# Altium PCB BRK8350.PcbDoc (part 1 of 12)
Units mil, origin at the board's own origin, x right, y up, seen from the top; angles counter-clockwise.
Board outline 9448.82 x 5905.51 mil, 8 copper layers (L1-TOP, L2-GND, L3-SIG, L4-GND, L5-PWR, L6-PWR, L7-GND, L8-BOT), stack 57.69 mil thick; 288 components, 543 nets, 1891 pads, 2032 vias.
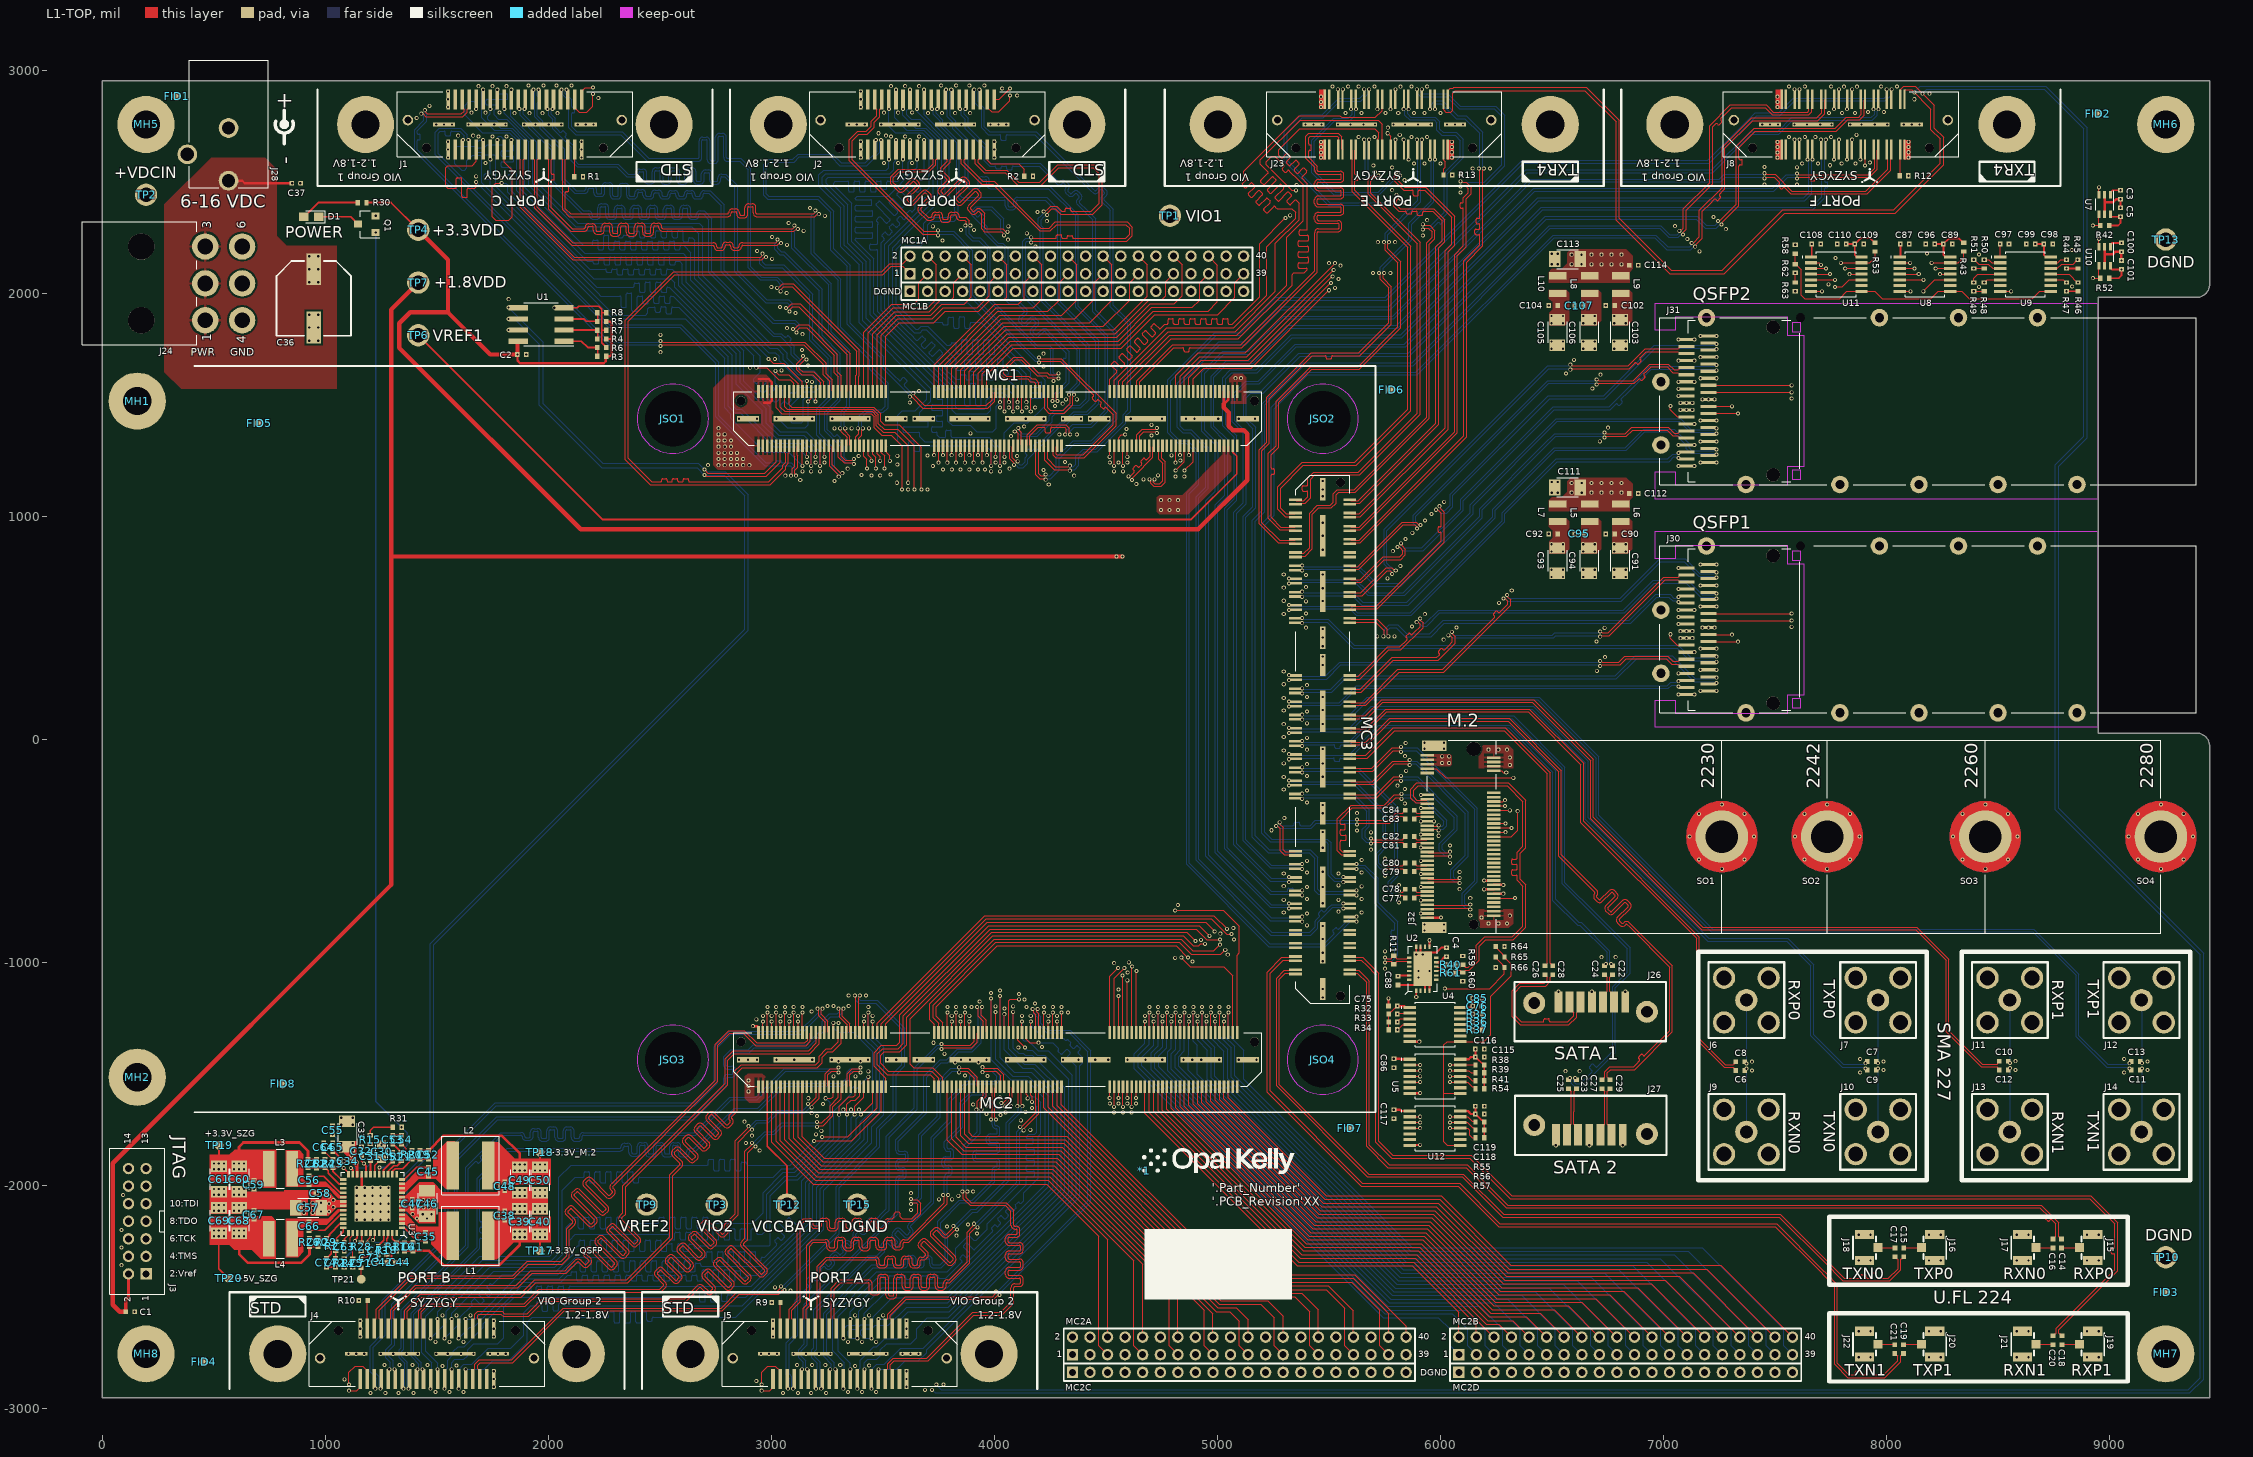
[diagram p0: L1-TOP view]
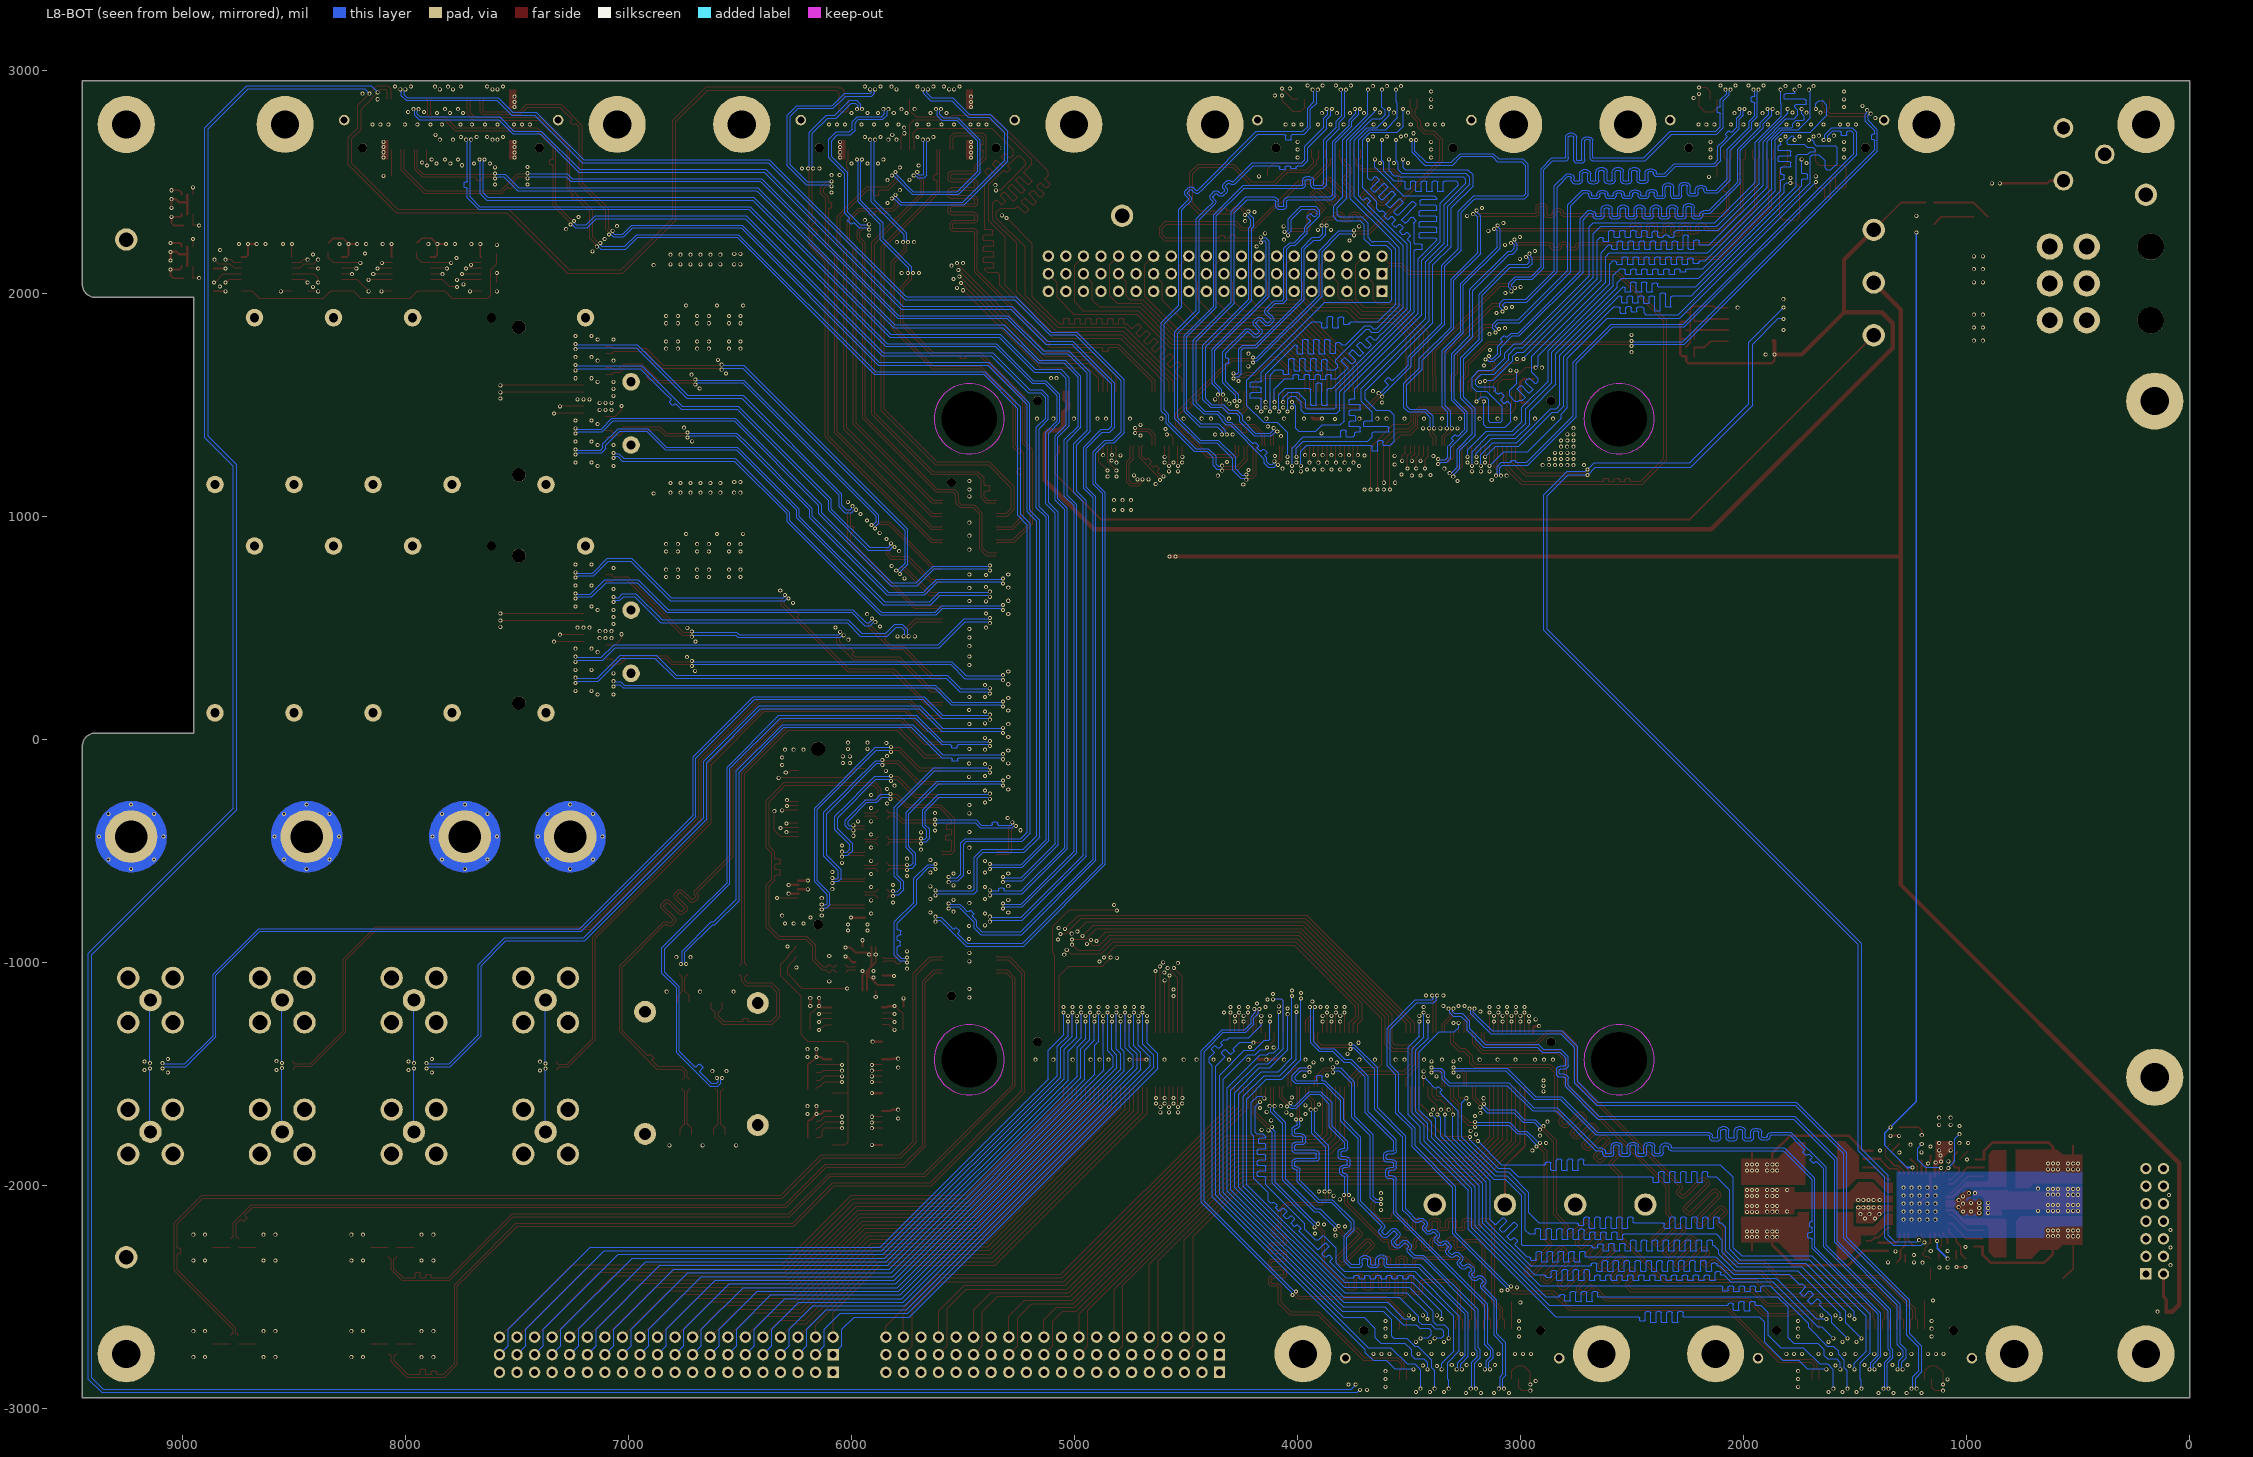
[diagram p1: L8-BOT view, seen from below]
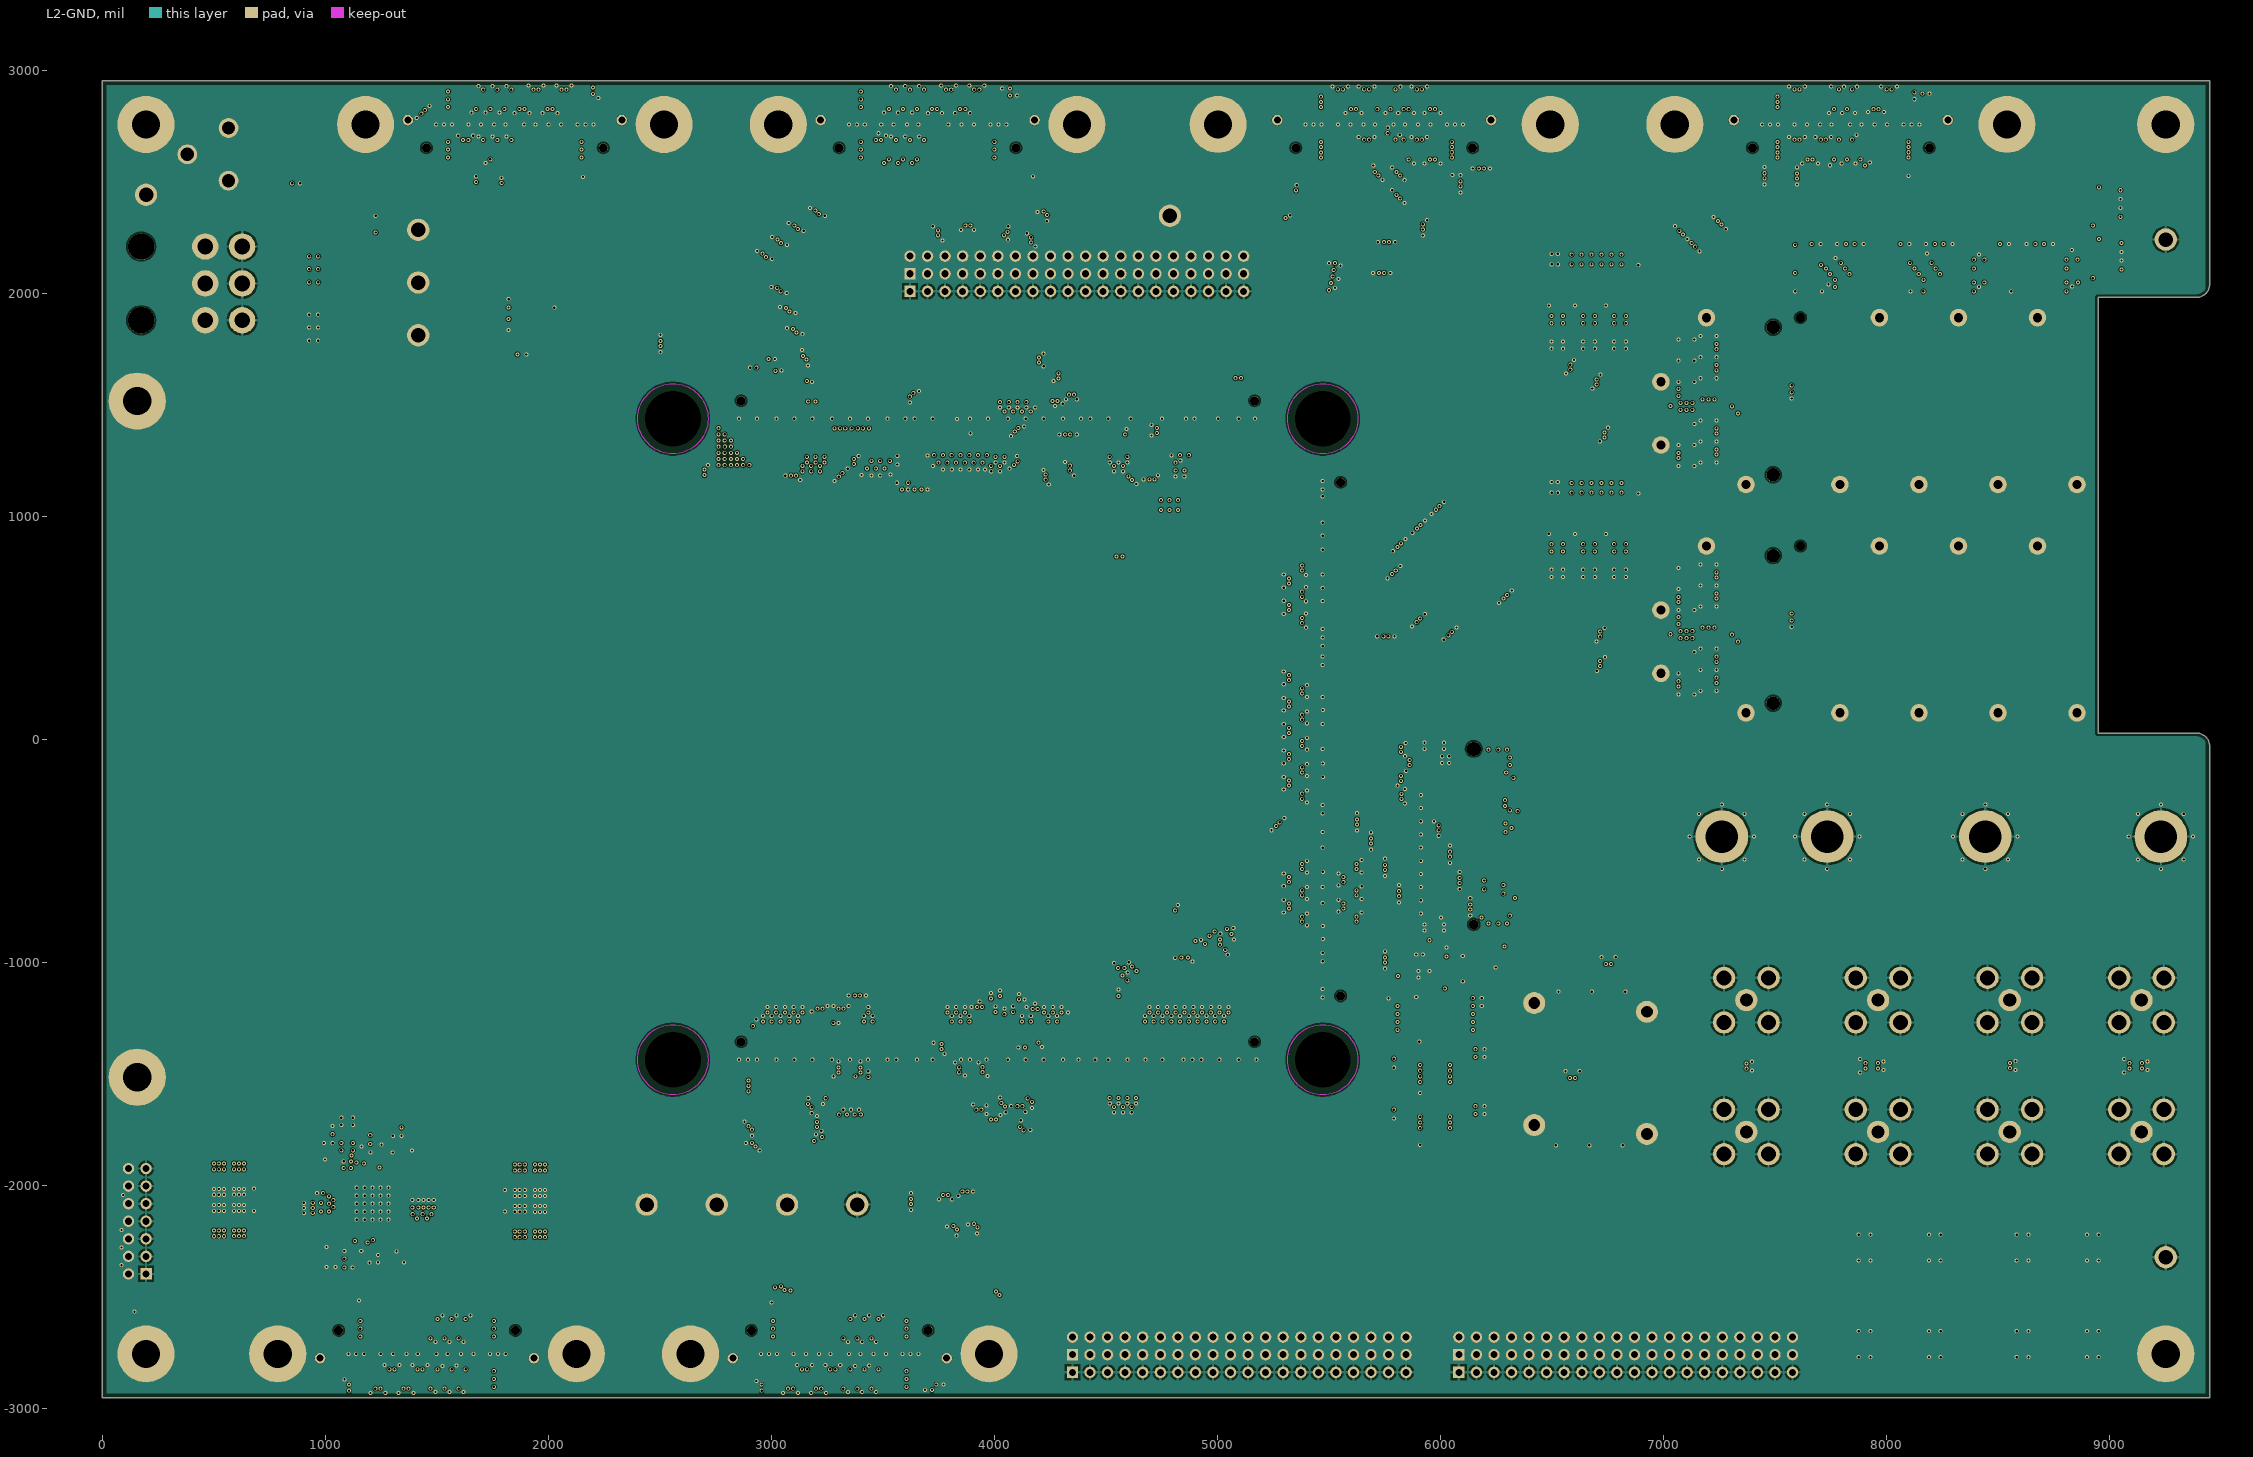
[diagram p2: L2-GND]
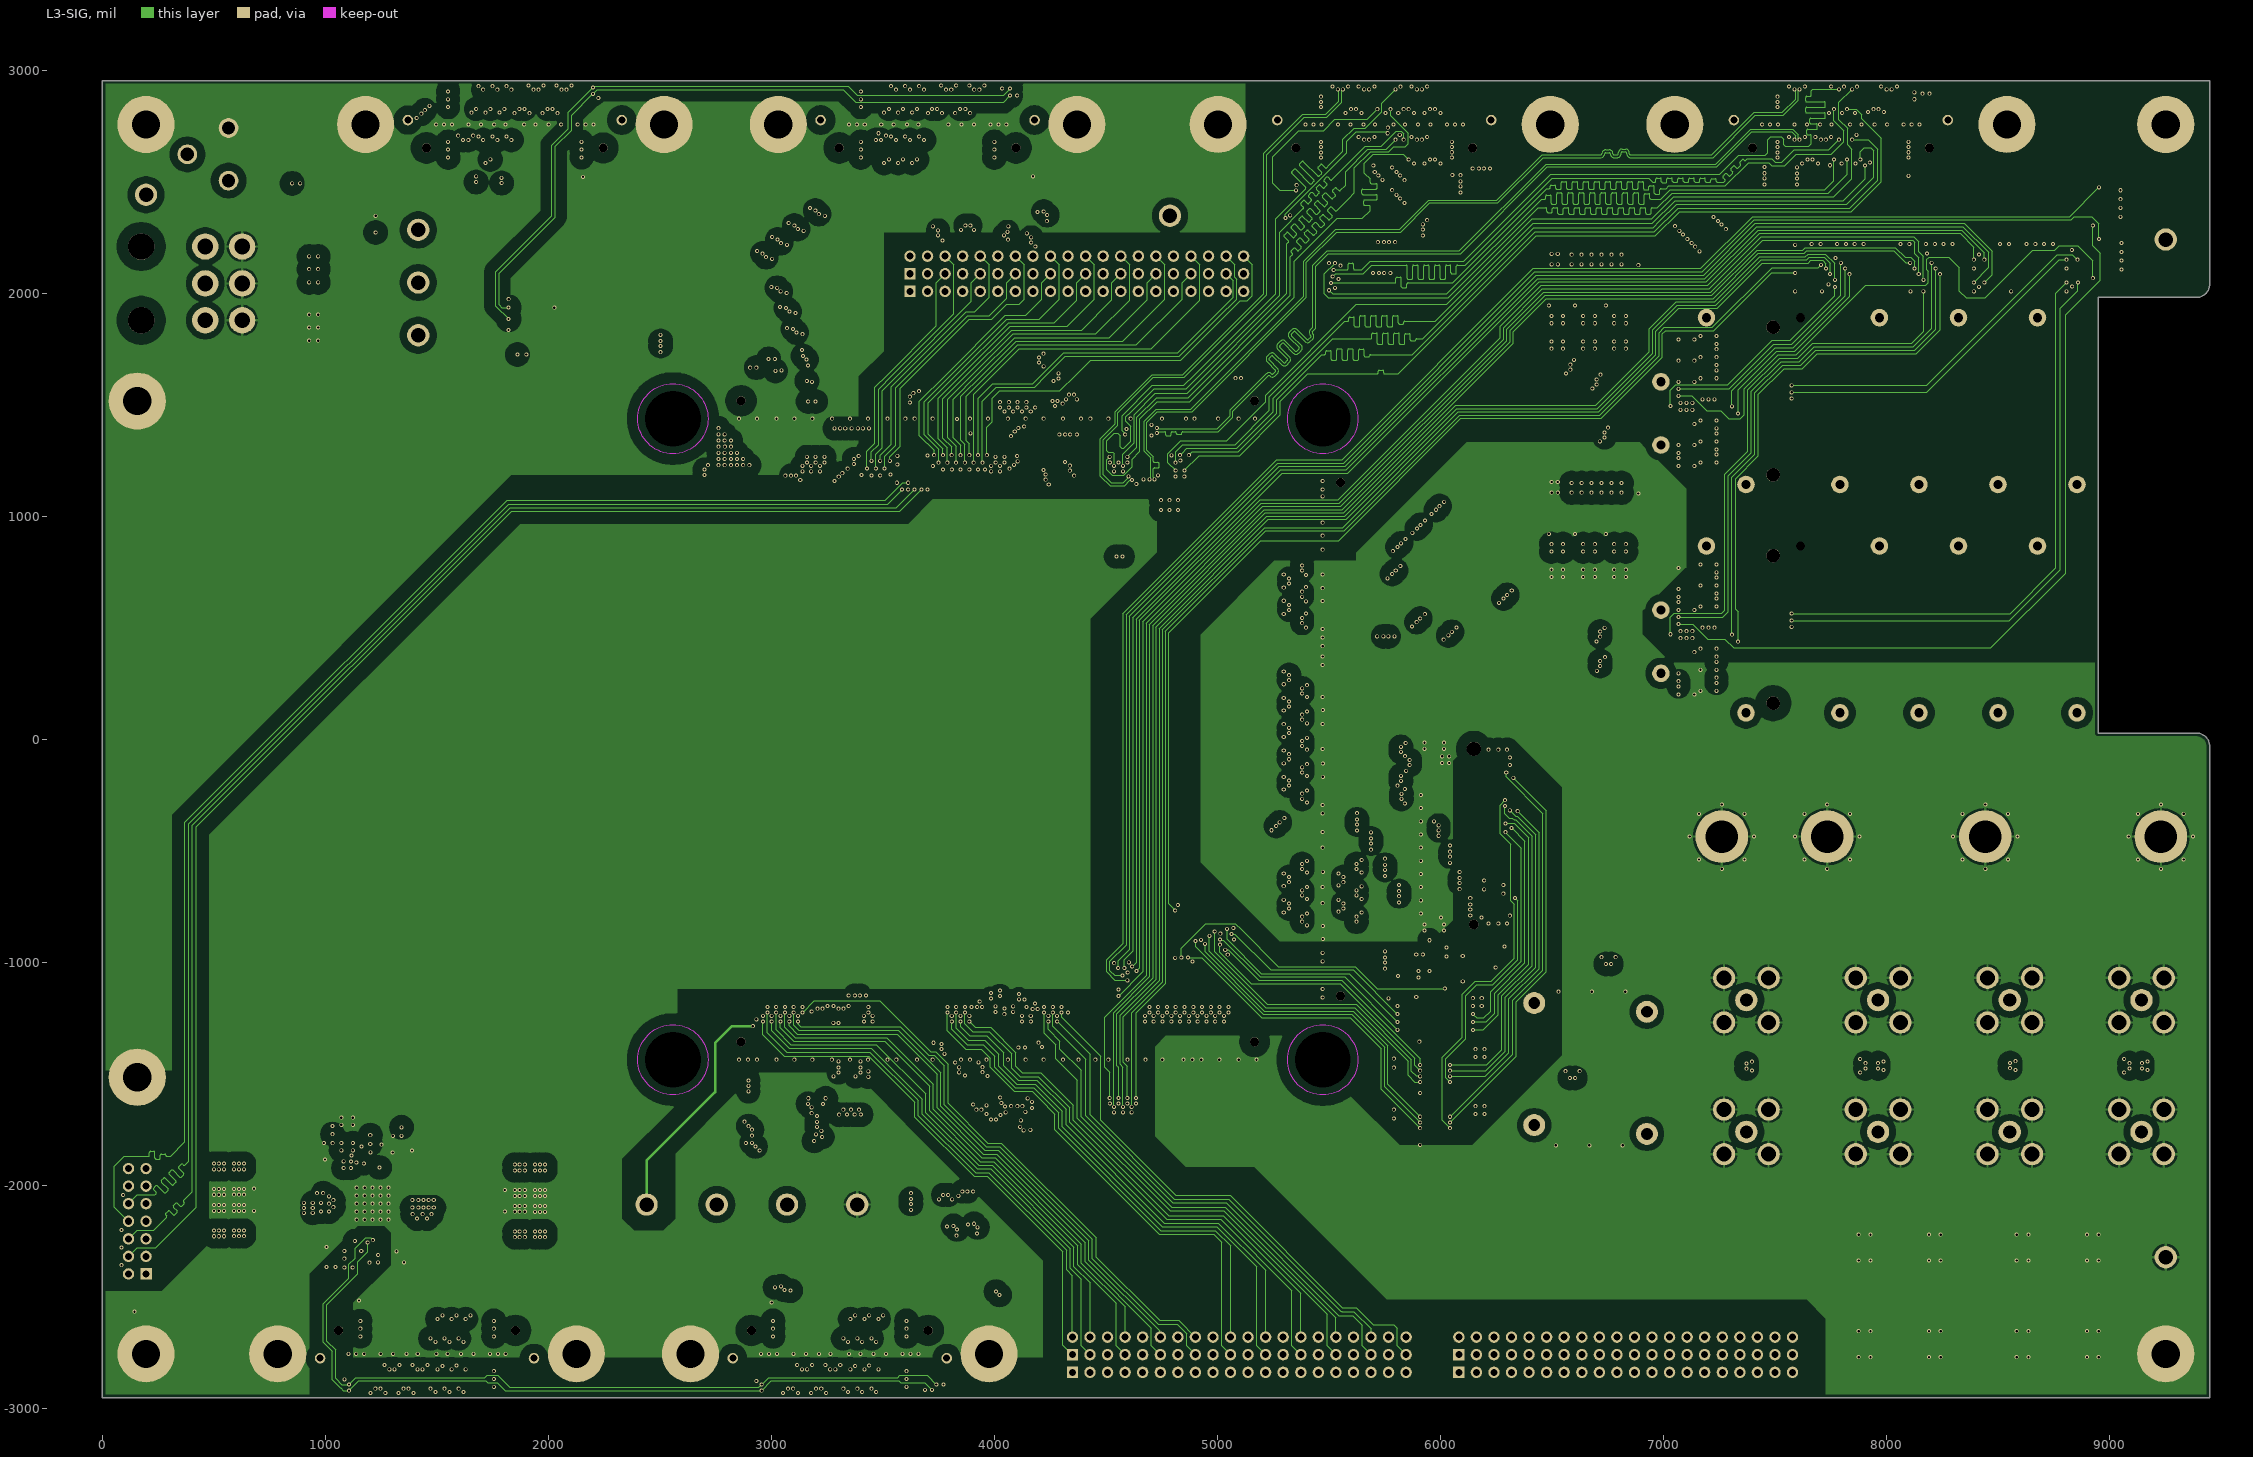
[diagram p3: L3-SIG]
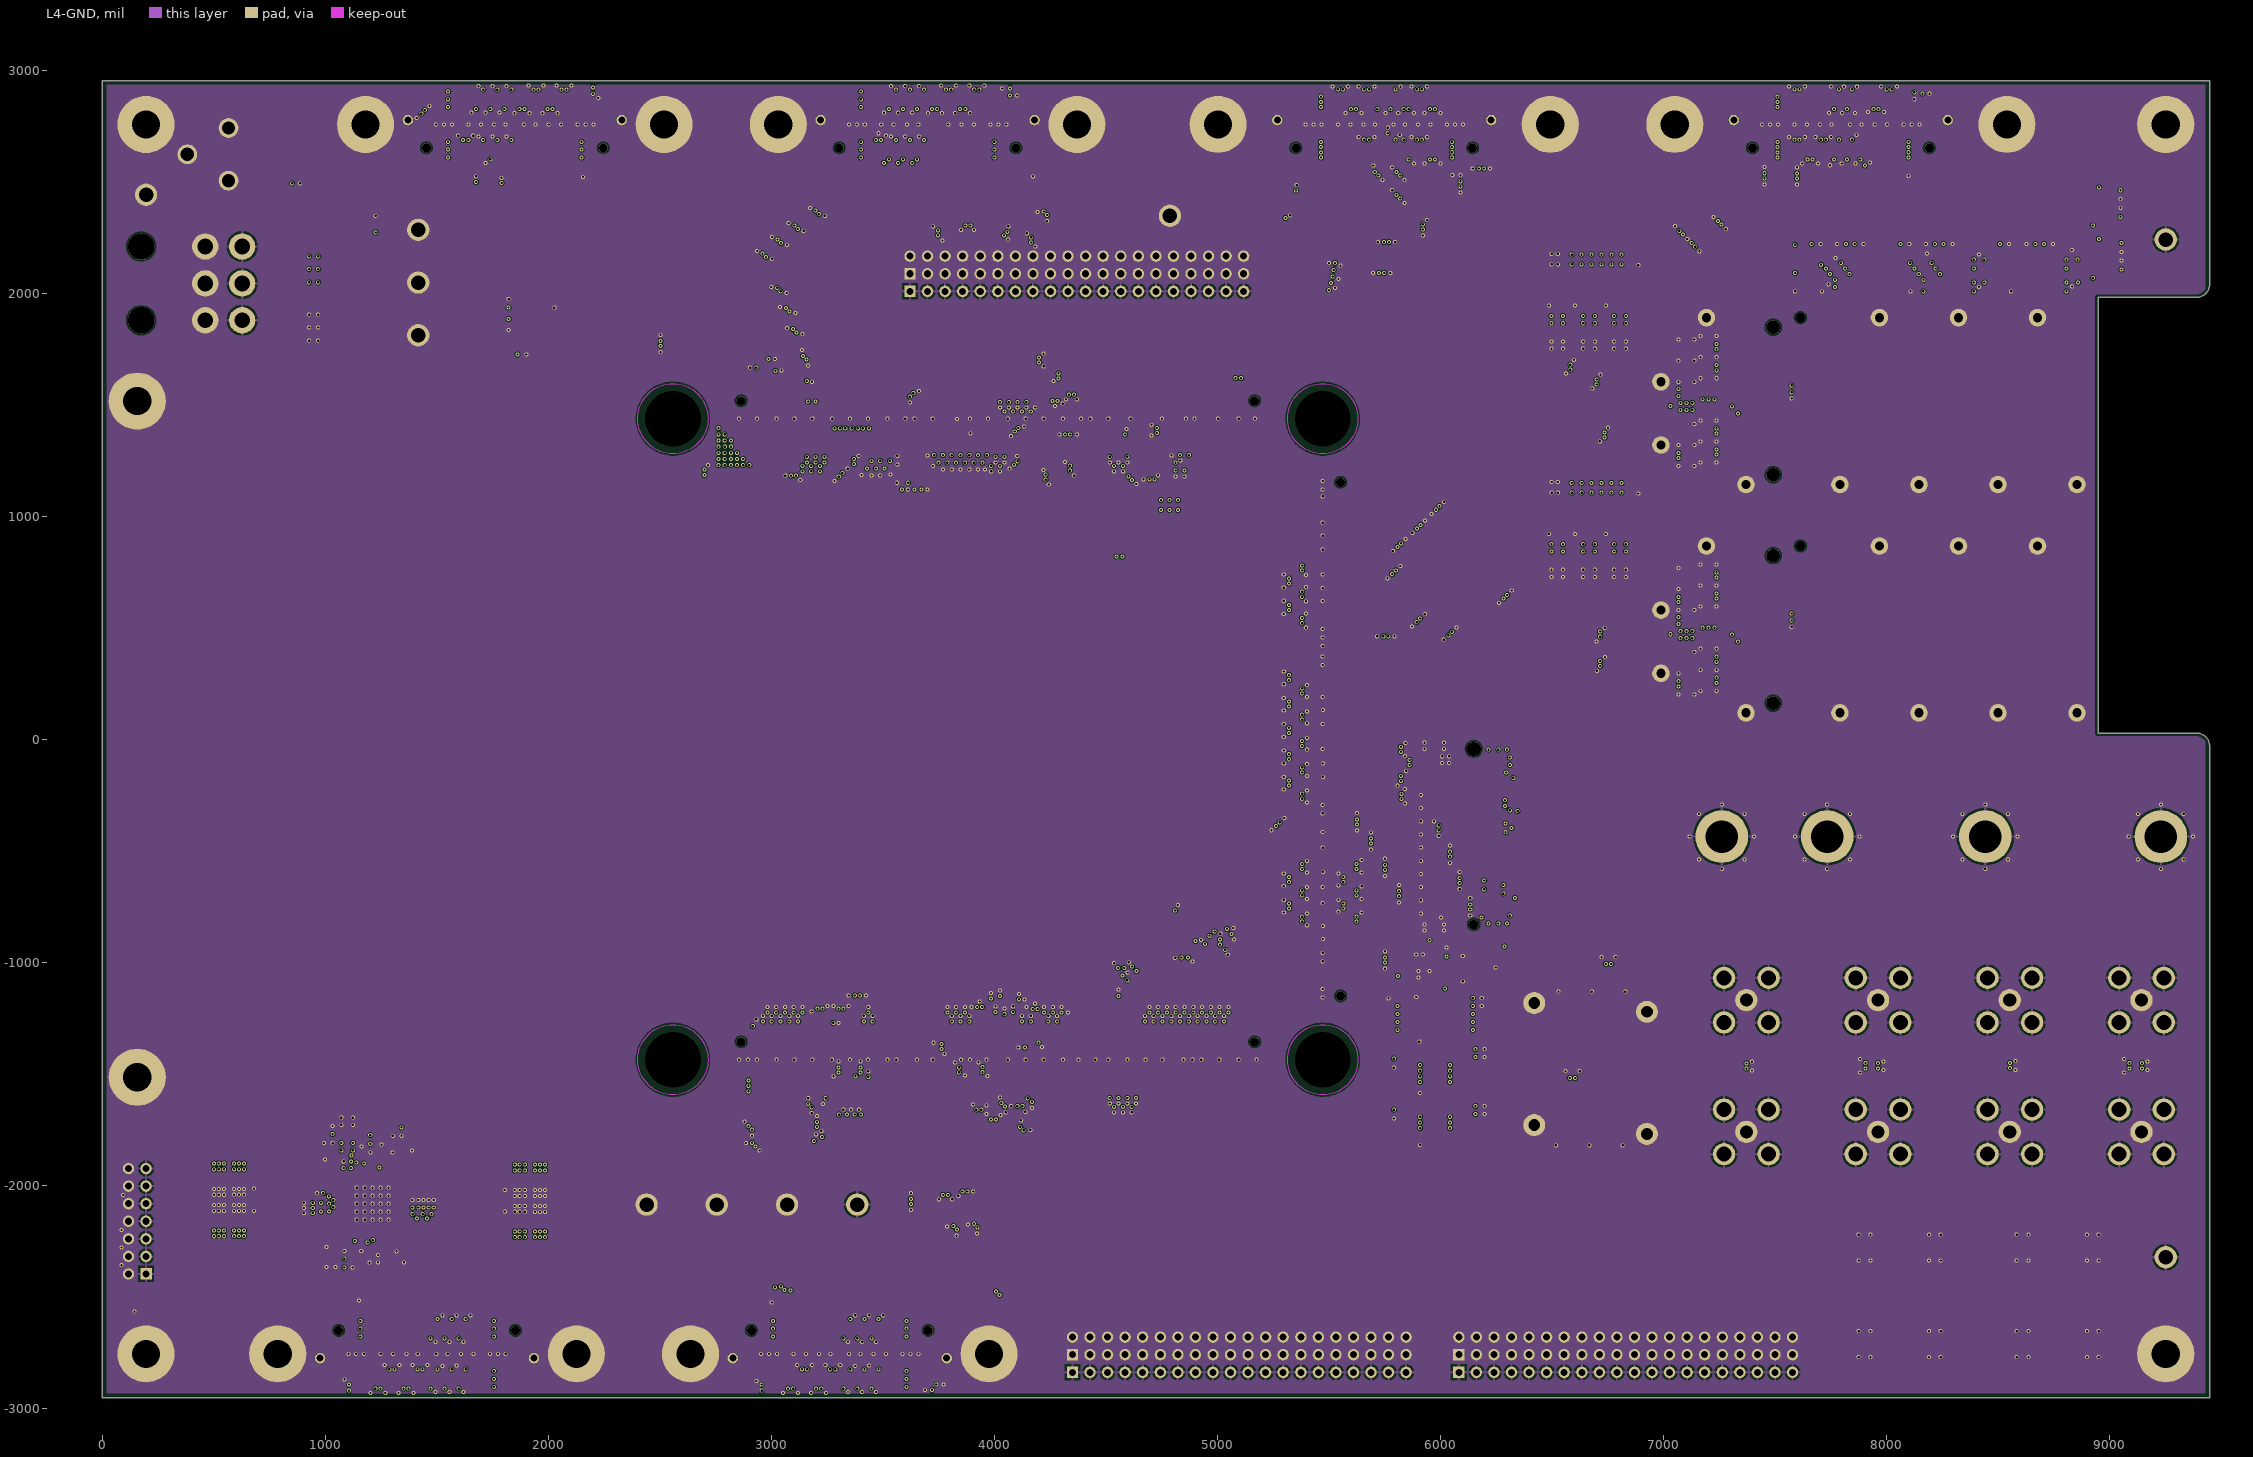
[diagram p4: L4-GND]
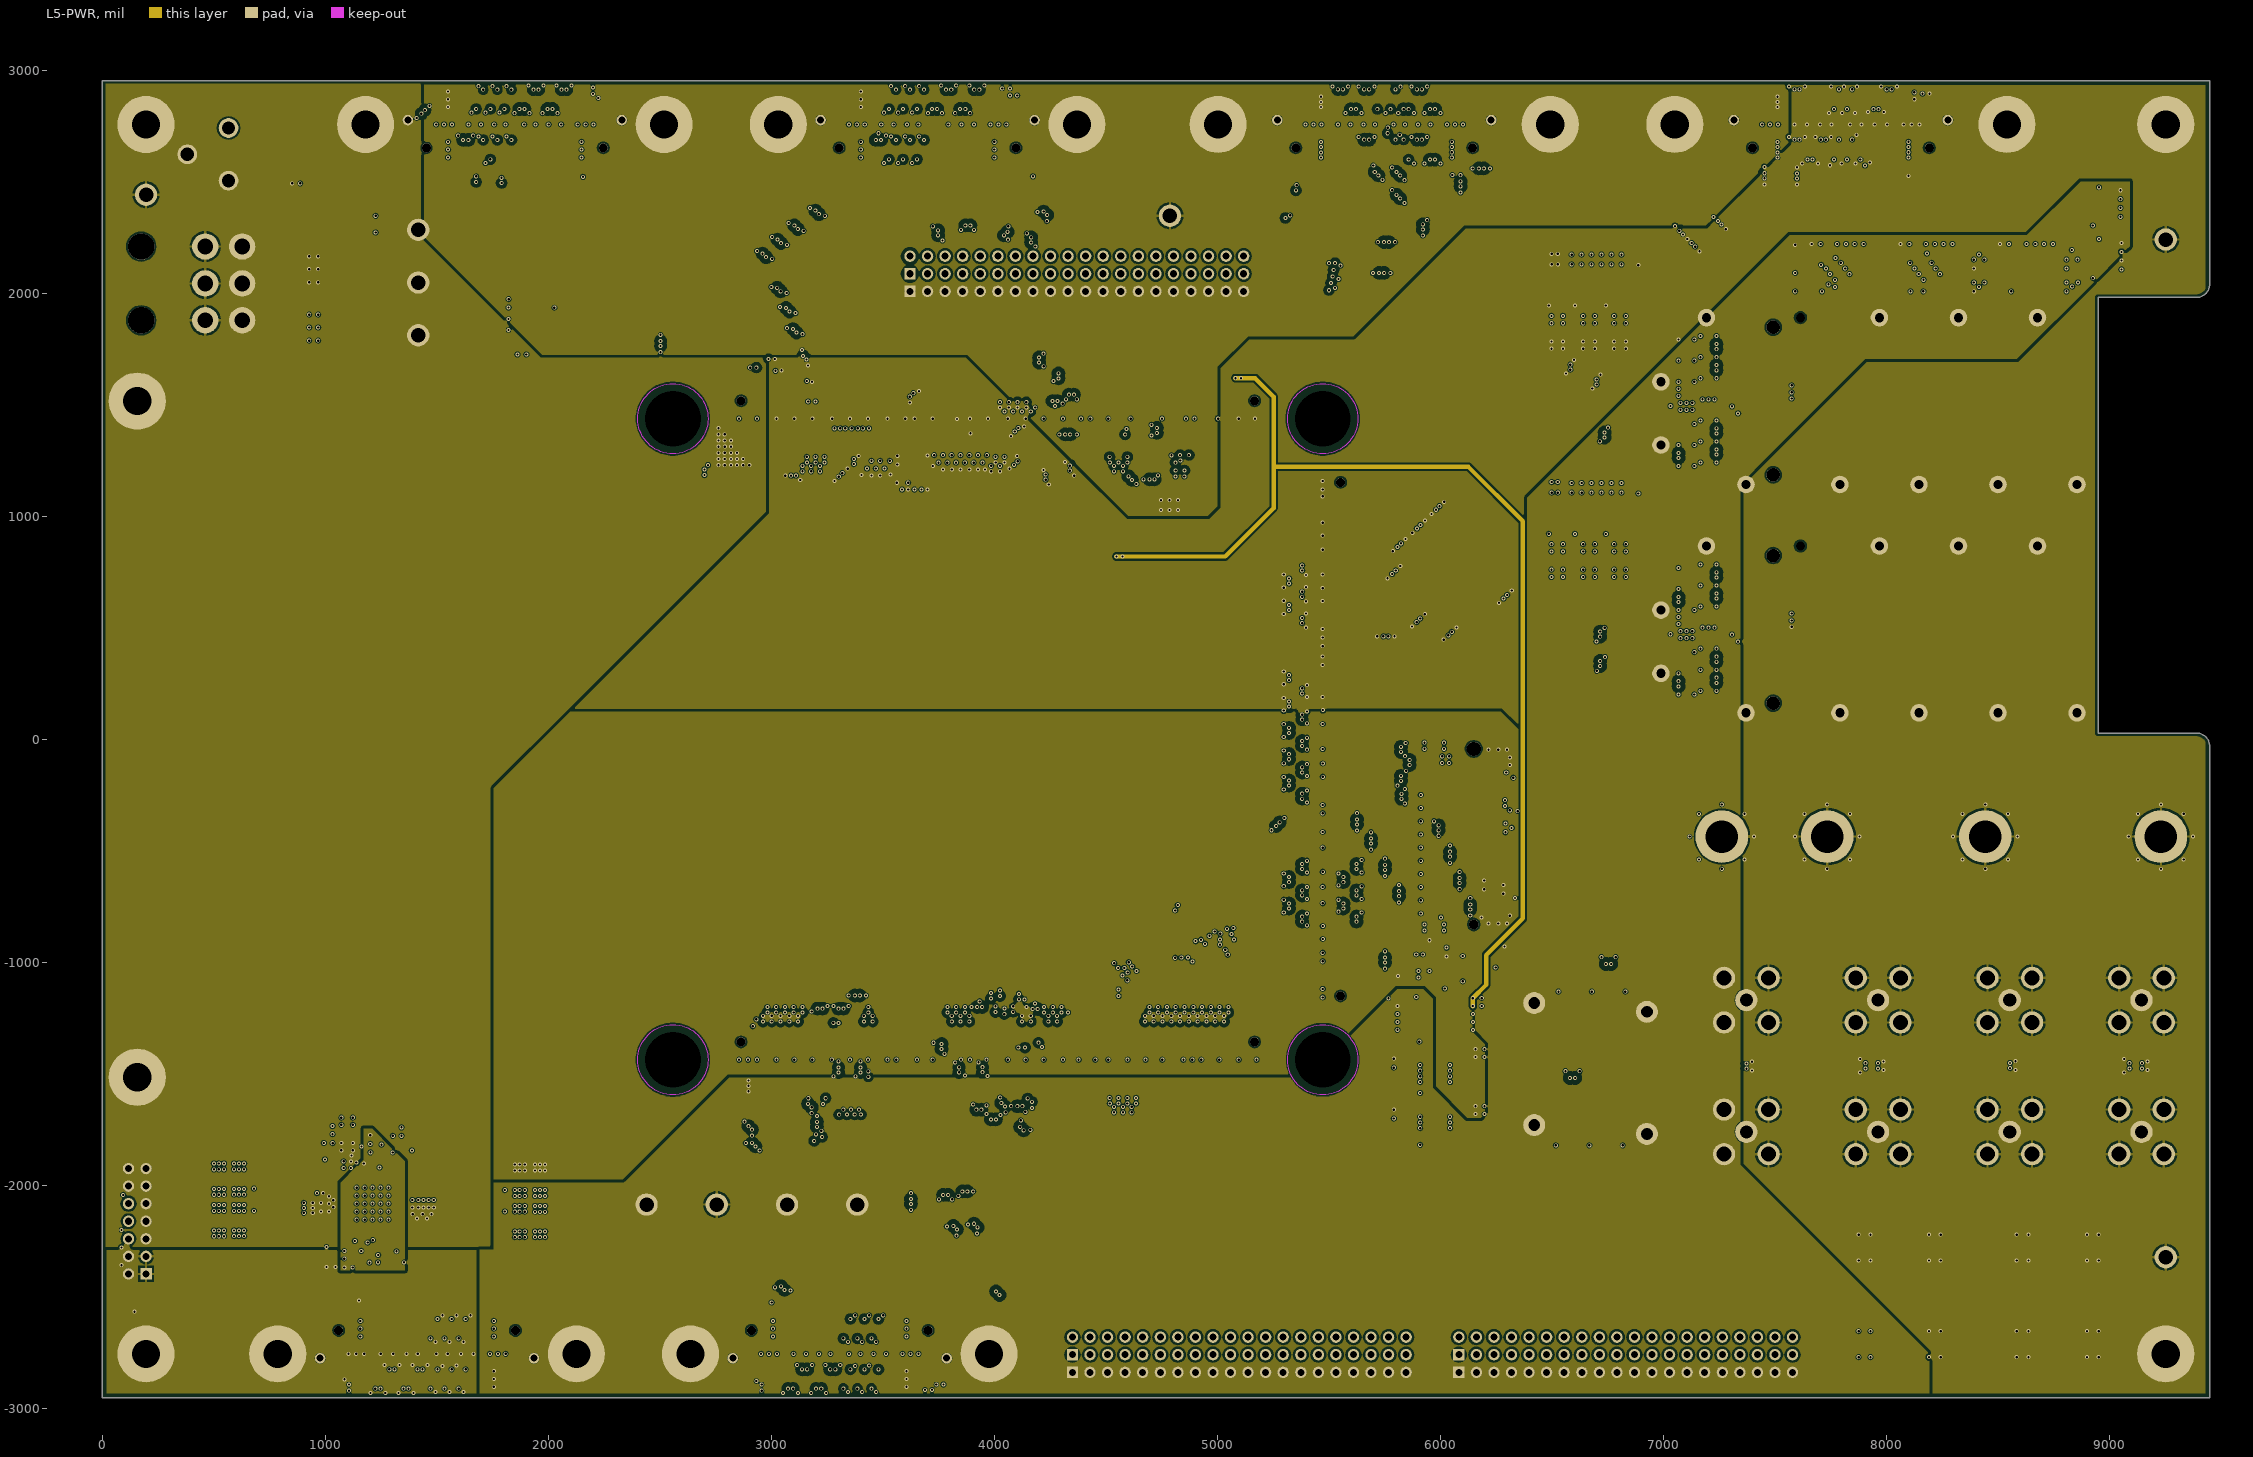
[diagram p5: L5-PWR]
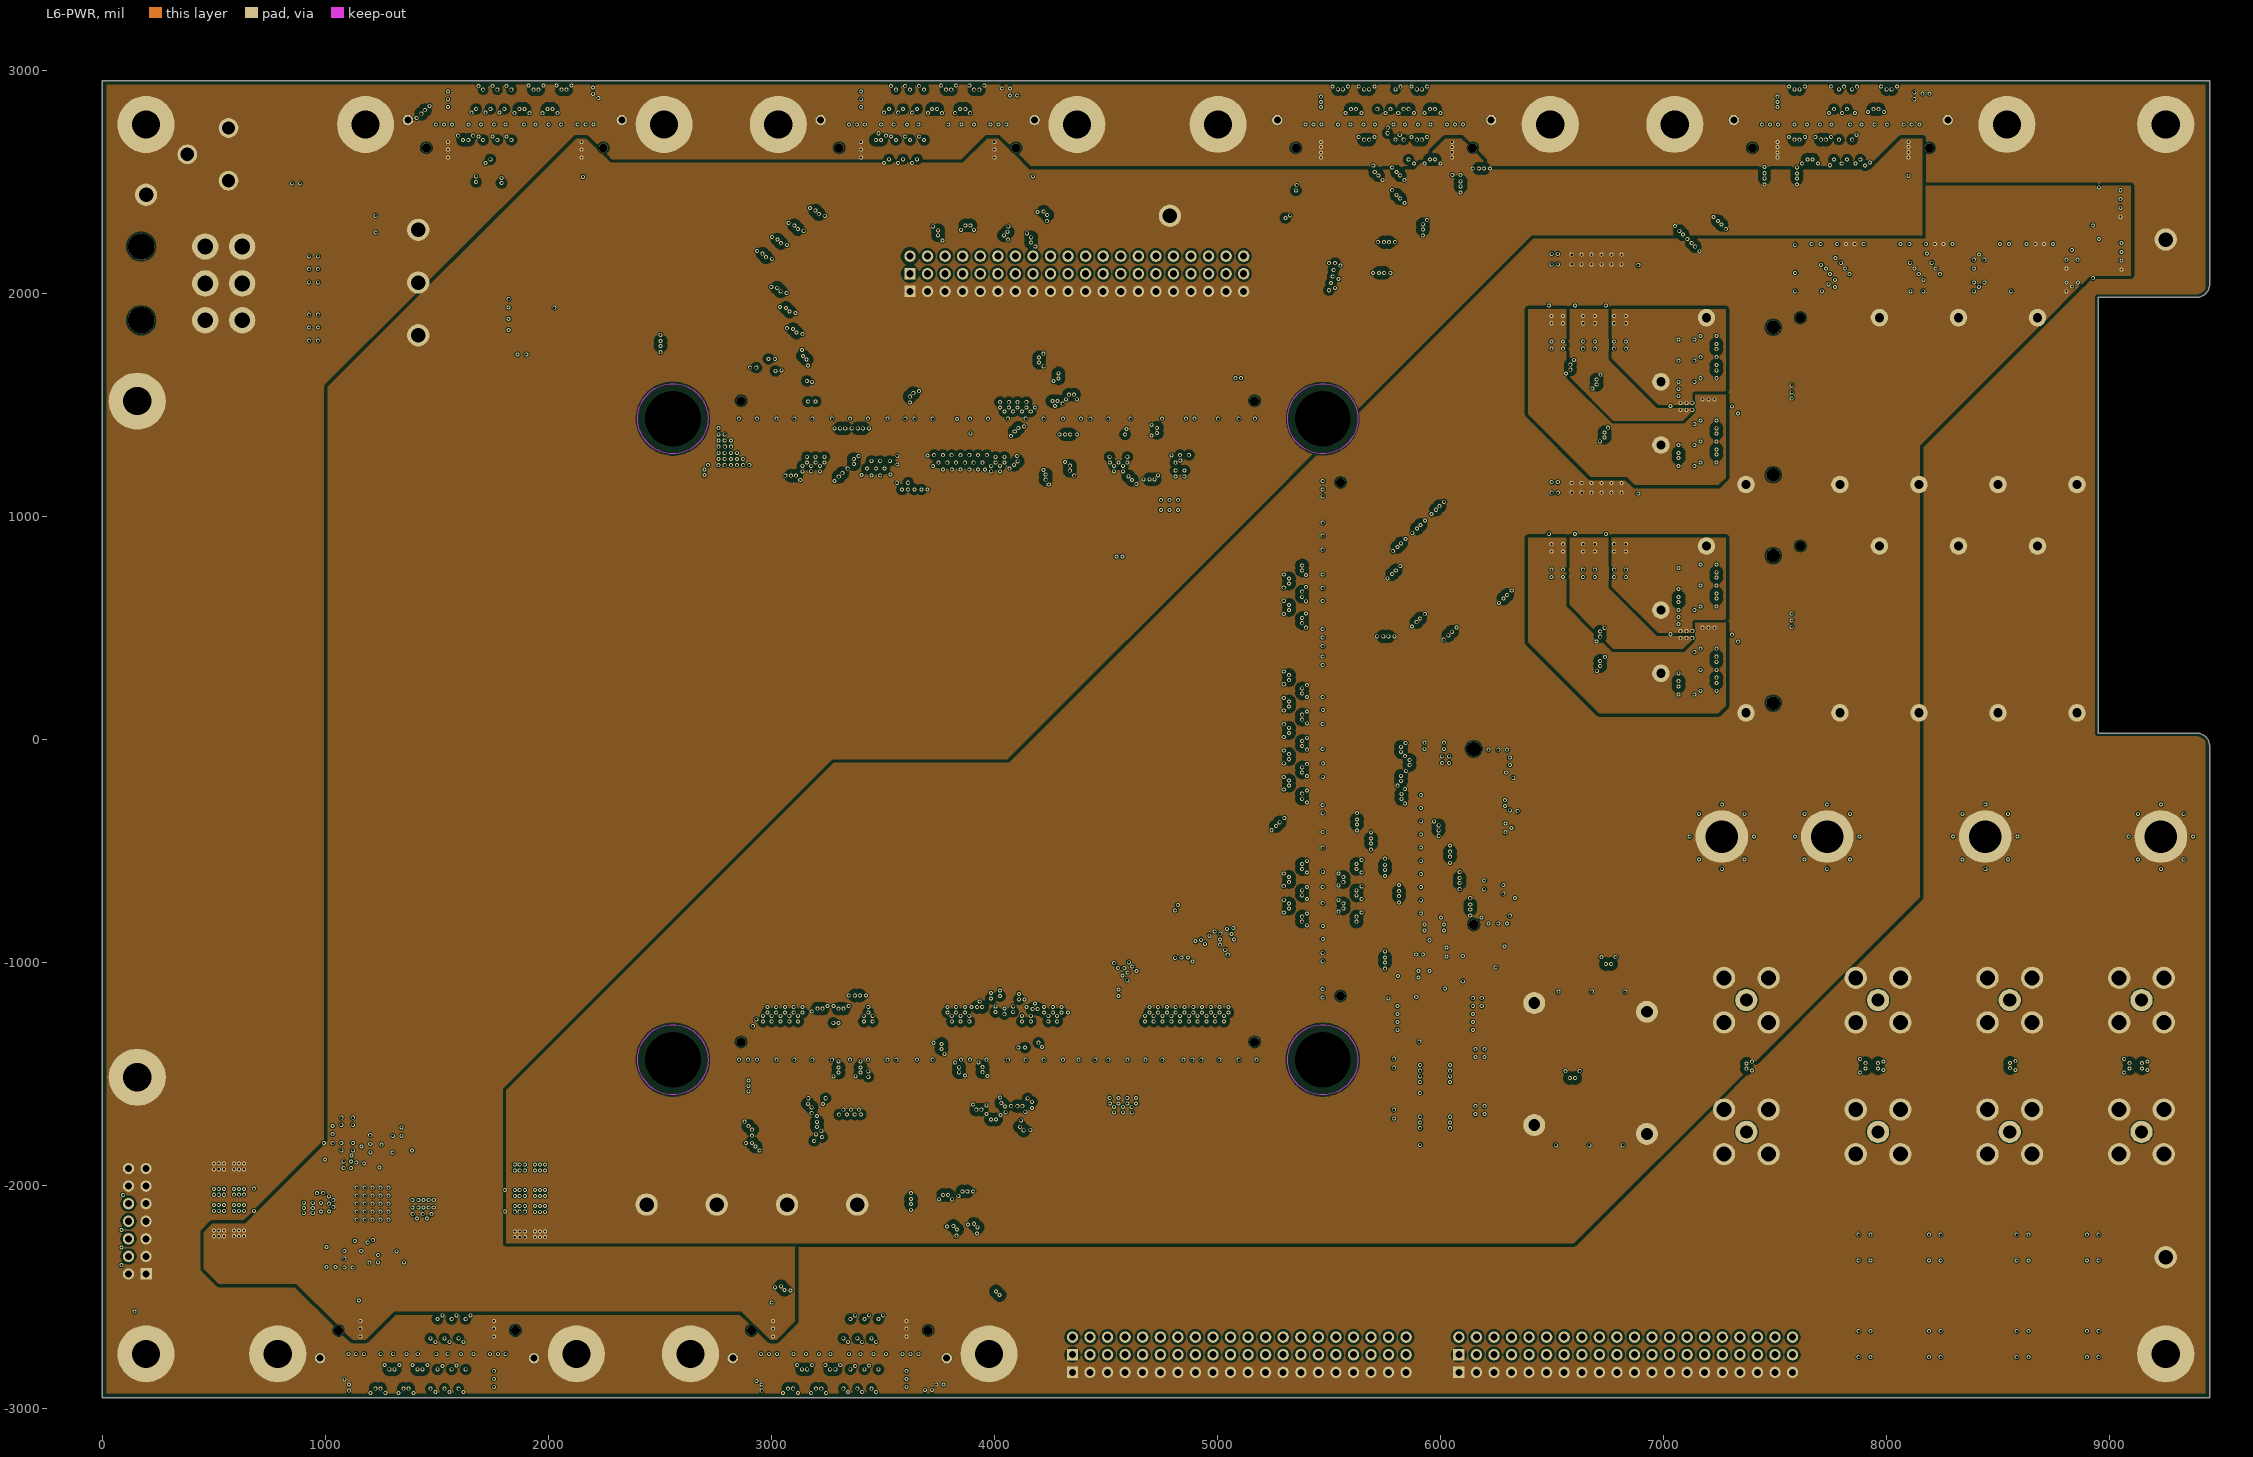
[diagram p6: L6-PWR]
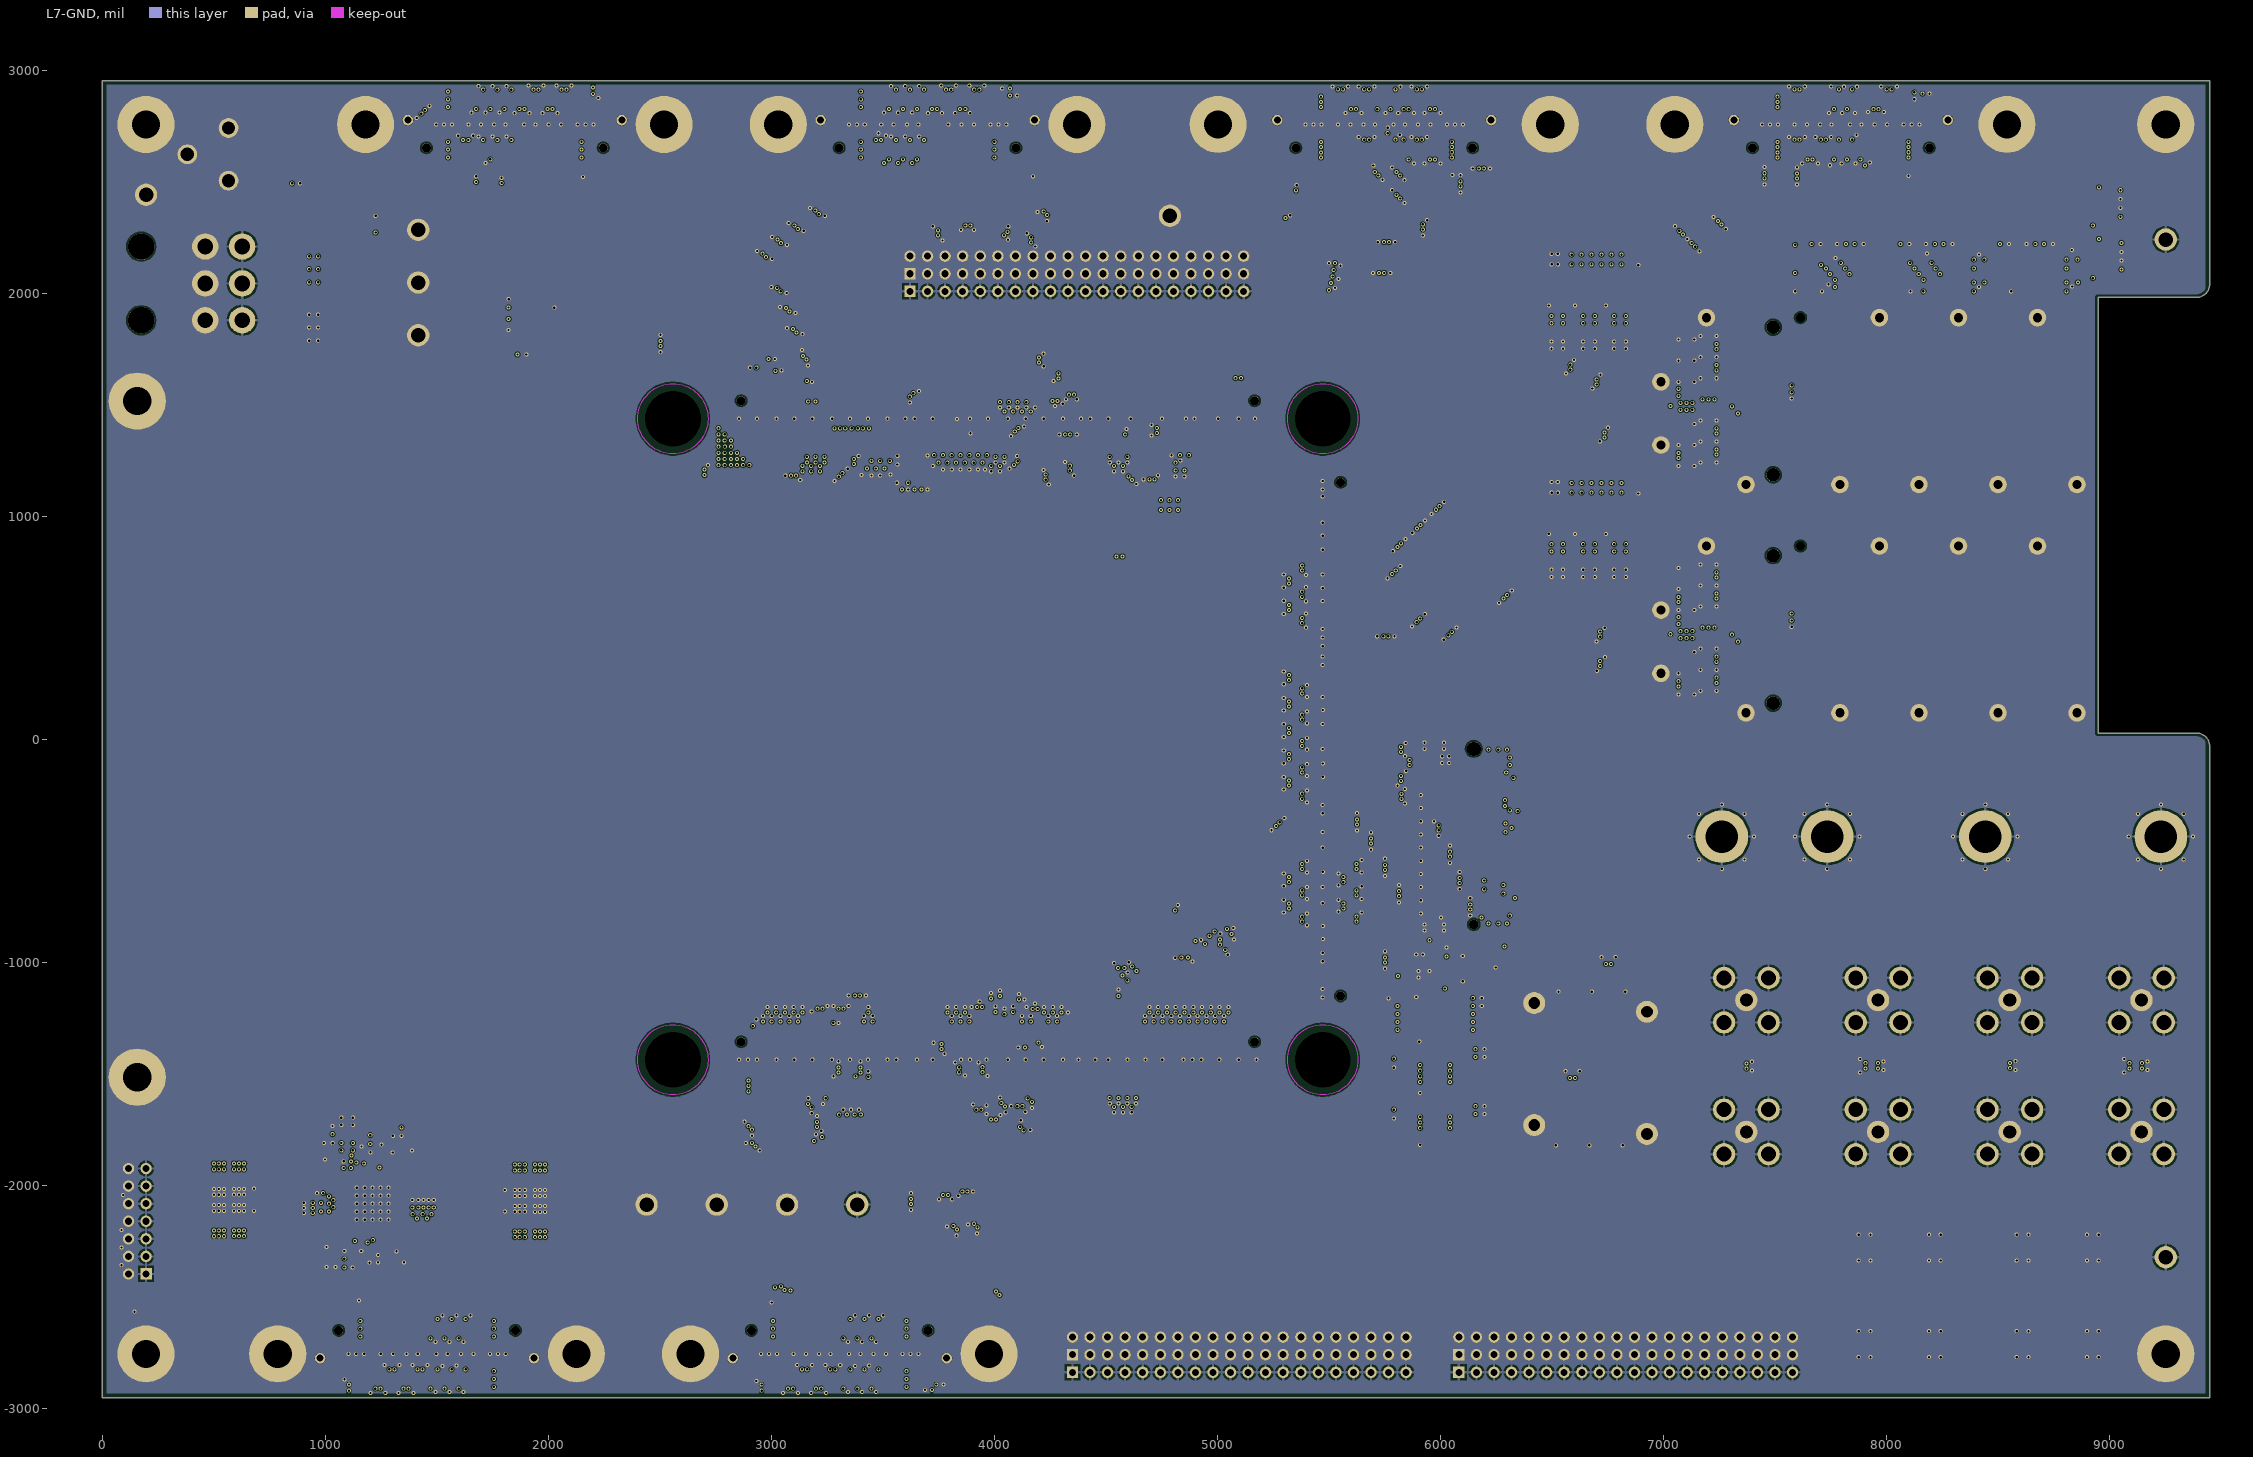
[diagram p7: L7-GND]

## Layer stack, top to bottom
Top Solder: solder mask 0.8, Solder Resist, Dk 0
L1-TOP: signal copper 1.4
Dielectric 2: prepreg 3.19, IT180A, Dk 3.79
L2-GND: signal copper 1.4
Dielectric 1: core 10.41, IT180A, Dk 4.35
L3-SIG: signal copper 1.4
Dielectric 3: prepreg 3.74, IT180A, Dk 3.61
L4-GND: signal copper 1.4
Dielectric 5: core 11.81, IT180A, Dk 4.35
L5-PWR: signal copper 1.4
Dielectric 6: prepreg 3.74, IT180A, Dk 3.61
L6-PWR: signal copper 1.4
Dielectric 7: core 10.41, IT180A, Dk 4.35
L7-GND: signal copper 1.4
Dielectric 4: prepreg 3.19, IT180A, Dk 3.79
L8-BOT: signal copper 1.4
Solder Side: solder mask 0.8, Solder Resist, Dk 0

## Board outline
0,-2952.76 0,2952.76 9448.82,2952.76 9448.82,2039.37 cw(c9389.76,2039.37) 9389.76,1980.32 8948.82,1980.32 8948.82,27.56 9389.76,27.56 cw(c9389.76,-31.5) 9448.82,-31.5 9448.82,-2952.76

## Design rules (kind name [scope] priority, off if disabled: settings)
BoardOutlineClearance [All] p1: gap=15 ignorepadtopadclearanceinfootprint=FALSE
Clearance Clearance_Diff_Diff [InDifferentialPairClass('100ohm_Diff') and not (TouchesRoom('MC3') or TouchesRoom('MC2A') or TouchesRoom('MC1A') or TouchesRoom('PORTE') or TouchesRoom('PORTF') or TouchesRoom('PORTD') or TouchesRoom('PORTC') or TouchesRoom('PORTB') or TouchesRoom('PORTA') or TouchesRoom('M.2') or HasFootprint('RESC1005X06A') or HasFootprint('CAPC1005X06A') or TouchesRoom('MC1') or TouchesRoom('MC2')) vs InDifferentialPairClass('100ohm_Diff') and not (TouchesRoom('MC3') or TouchesRoom('MC2A') or TouchesRoom('MC1A') or TouchesRoom('PORTE') or TouchesRoom('PORTF') or TouchesRoom('PORTD') or TouchesRoom('PORTC') or TouchesRoom('PORTB') or TouchesRoom('PORTA') or TouchesRoom('M.2') or HasFootprint('RESC1005X06A') or HasFootprint('CAPC1005X06A') or TouchesRoom('MC1') or TouchesRoom('MC2'))] p1: gap=25 ignorepadtopadclearanceinfootprint=FALSE
Clearance Clearance_SE_SE [InNetClass('50ohm') and not (TouchesRoom('MC2A') or TouchesRoom('MC1A') or TouchesRoom('PORTE') or TouchesRoom('PORTF') or TouchesRoom('PORTD') or TouchesRoom('PORTC') or TouchesRoom('PORTB') or TouchesRoom('PORTA') or TouchesRoom('MC1') or TouchesRoom('MC2')) vs InNetClass('50ohm') and not (TouchesRoom('MC2A') or TouchesRoom('MC1A') or TouchesRoom('PORTE') or TouchesRoom('PORTF') or TouchesRoom('PORTD') or TouchesRoom('PORTC') or TouchesRoom('PORTB') or TouchesRoom('PORTA') or TouchesRoom('MC1') or TouchesRoom('MC2'))] p2: gap=5 ignorepadtopadclearanceinfootprint=FALSE except(4.5: SMDPad-Via Via-Via; 8: Arc-Poly SMDPad-Poly THPad-Poly Via-Fill Via-Poly Via-Region Fill-Poly Poly-Region Poly-Text Poly-Hole; 10: Track-Poly; 12: Arc-Arc Arc-Track Track-Track; 15: Poly-Poly)
Clearance Clearance_Fid [HasFootprint('FID1MM/2MM-SS')] p3: gap=8 ignorepadtopadclearanceinfootprint=FALSE except(30: Arc-Fill Arc-Poly Arc-Region Track-Fill Track-Poly Track-Region SMDPad-Fill SMDPad-Poly SMDPad-Region THPad-Fill THPad-Poly THPad-Region Via-Fill Via-Poly Via-Region Fill-Fill Fill-Poly Fill-Region Poly-Poly Poly-Region Region-Region)
Clearance Clearance_DiffPair_Poly [InDifferentialPairClass('100ohm_Diff') vs InPolygon and not InNet('DGND')] p4: gap=5 ignorepadtopadclearanceinfootprint=FALSE except(4.5: SMDPad-Via Via-Via; 7: Via-Fill; 8: Via-Region Poly-Region Poly-Text Poly-Hole; 25: Arc-Poly Track-Poly SMDPad-Poly THPad-Poly Via-Poly Fill-Poly Poly-Poly)
Clearance Clearance_SE_Poly [InNetClass('50ohm') vs InPolygon and not InNet('DGND')] p5: gap=5 ignorepadtopadclearanceinfootprint=FALSE except(4.5: SMDPad-Via Via-Via; 8: Via-Fill Via-Region Poly-Region Poly-Text Poly-Hole; 20: Arc-Poly Track-Poly SMDPad-Poly THPad-Poly Via-Poly Fill-Poly Poly-Poly)
Clearance Clearance_GPIO_Space [InNetClass('GPIO_Space') vs InNetClass('GPIO_Space')] p6: gap=5 ignorepadtopadclearanceinfootprint=FALSE except(4.5: SMDPad-Via Via-Via; 8: Arc-Poly SMDPad-Poly THPad-Poly Via-Fill Via-Poly Via-Region Fill-Poly Poly-Region Poly-Text Poly-Hole; 10: Arc-Track Track-Track Track-Poly; 15: Poly-Poly)
Clearance Clearance_Filler_poly [OnLayer('L3-SIG') and inpolygon] p7: gap=50 ignorepadtopadclearanceinfootprint=FALSE
Clearance [All] p8: gap=5 ignorepadtopadclearanceinfootprint=FALSE except(4.5: SMDPad-Via Via-Via; 8: Arc-Poly SMDPad-Poly THPad-Poly Via-Fill Via-Poly Via-Region Fill-Poly Poly-Region Poly-Text Poly-Hole; 10: Track-Poly; 15: Poly-Poly)
DiffPairsRouting 100ohm_Diff [InDifferentialPairClass('100ohm_Diff')] p1: maxlimit=8.4 minlimit=1 mostfreqgap=1 toplayer_mingap=8.4 toplayer_prefgap=8.4 toplayer_minwidth=4.2 toplayer_maxwidth=4.2 toplayer_prefwidth=4.2 midlayer1_maxgap=1 midlayer1_minwidth=1 midlayer1_maxwidth=1 midlayer1_prefwidth=1 midlayer2_mingap=8.4 midlayer2_prefgap=8.4 midlayer2_minwidth=4.25 midlayer2_maxwidth=4.25 midlayer2_prefwidth=4.25 midlayer3_maxgap=1 midlayer3_minwidth=1 midlayer3_maxwidth=1 midlayer3_prefwidth=1 midlayer4_maxgap=1 midlayer4_minwidth=1 midlayer4_maxwidth=1 midlayer4_prefwidth=1 midlayer5_maxgap=1 midlayer5_minwidth=1 midlayer5_maxwidth=1 midlayer5_prefwidth=1 midlayer6_maxgap=1 midlayer6_minwidth=1 midlayer6_maxwidth=1 midlayer6_prefwidth=1 bottomlayer_mingap=8.4 bottomlayer_prefgap=8.4 bottomlayer_minwidth=4.2 bottomlayer_maxwidth=4.2 bottomlayer_prefwidth=4.2 maxuncoupledlength=350
FabricationTestPointUsage TestPointUsage [All] p1: valid=0 allowmultiple=FALSE
FabricationTestpoint Testpoint [All] p1: side=3 testpointundercomponent=TRUE minsize=40 maxsize=100 preferedsize=60 minholesize=0 maxholesize=40 preferedholesize=32 testpointgrid=1 allowsidetop=TRUE allowsidebottom=TRUE usegrid=TRUE gridtolerance=0.01
HoleSize [All] p1: absolutevalues=TRUE maxlimit=500 minlimit=10 maxpercent=80.000 minpercent=20.000
MatchedLengths MatchedLengths_SATA1 [InxSignalClass('xSignals_SATA1')] p1: tolerance=100 checknetsindiffpair=FALSE checkdiffpairvsdiffpair=TRUE checkxsignals=TRUE checkothers=TRUE
MatchedLengths MatchedLengths_SATA2 [InxSignalClass('xSignals_SATA2')] p2: tolerance=100 checknetsindiffpair=FALSE checkdiffpairvsdiffpair=TRUE checkxsignals=TRUE checkothers=TRUE
MatchedLengths MatchedLengths_JTAG [InxSignalClass('xSignals_JTAG')] p3: tolerance=10 checknetsindiffpair=FALSE checkdiffpairvsdiffpair=TRUE checkxsignals=TRUE checkothers=TRUE
MatchedLengths MatchedLengths_xSignalPairs [InxSignalClass('All xSignals')] p4: tolerance=5 checknetsindiffpair=TRUE checkdiffpairvsdiffpair=FALSE checkxsignals=FALSE checkothers=FALSE
MatchedLengths okMatched_PortA [InxSignalClass('xSignals_PORTA')] p5: tolerance=100 checknetsindiffpair=FALSE checkdiffpairvsdiffpair=TRUE checkxsignals=TRUE checkothers=TRUE
MatchedLengths okMatched_PortB [InxSignalClass('xSignals_PORTB')] p6: tolerance=100 checknetsindiffpair=FALSE checkdiffpairvsdiffpair=TRUE checkxsignals=TRUE checkothers=TRUE
MatchedLengths okMatched_PortC [InxSignalClass('xSignals_PORTC')] p7: tolerance=100 checknetsindiffpair=FALSE checkdiffpairvsdiffpair=TRUE checkxsignals=TRUE checkothers=TRUE
MatchedLengths okMatched_PortD [InxSignalClass('xSignals_PORTD')] p8: tolerance=100 checknetsindiffpair=FALSE checkdiffpairvsdiffpair=TRUE checkxsignals=TRUE checkothers=TRUE
MatchedLengths okMatched_PortE [InxSignalClass('xSignals_PORTE')] p9: tolerance=100 checknetsindiffpair=FALSE checkdiffpairvsdiffpair=TRUE checkxsignals=TRUE checkothers=TRUE
MatchedLengths okMatched_PortF [InxSignalClass('xSignals_PORTF')] p10: tolerance=100 checknetsindiffpair=FALSE checkdiffpairvsdiffpair=TRUE checkxsignals=TRUE checkothers=TRUE
MinimumAnnularRing [All] p1: minimumring=4
MinimumSolderMaskSliver [All] p1: minsoldermaskwidth=1.9
PlaneClearance [All] p1: clearance=12
PlaneConnect PlaneConnectVia [IsVia] p1: planeconnectstyle=Direct reliefexpansion=20 reliefentries=4 reliefconductorwidth=15 reliefairgap=10
PlaneConnect [All] p2: planeconnectstyle=Relief reliefexpansion=20 reliefentries=4 reliefconductorwidth=15 reliefairgap=10
PolygonConnect PolygonConnectTH-Override [HasFootprint('CUI-PJ102A')] p1: connectstyle=Direct reliefconductorwidth=10 reliefentries=4 polygonreliefangle="90 Angle" airgapwidth=10
PolygonConnect "Via Connect" [IsVia] p2: connectstyle=Direct reliefconductorwidth=10 reliefentries=4 polygonreliefangle="90 Angle" airgapwidth=10
PolygonConnect PolygonConnectTH [IsThruPin] p3: connectstyle=Relief reliefconductorwidth=12 reliefentries=4 polygonreliefangle="90 Angle" airgapwidth=10
PolygonConnect PolygonConnectPAD [(IsPad and (OnTop or OnBottom)) and (not (InComponent('MC1') or InComponent('MC2') or InComponent('MC3') or InComponent('J32')))] p4: connectstyle=Direct reliefconductorwidth=12 reliefentries=4 polygonreliefangle="90 Angle" airgapwidth=15
PolygonConnect [All] p5: connectstyle=Relief reliefconductorwidth=10 reliefentries=4 polygonreliefangle="90 Angle" airgapwidth=12
ReturnPath [All] p1: impedanceprofileid={57DEC265-C755-4805-A29F-7F8F814E9868} _gaplimit=0
RoomDefinition PORTB [False] p1: confinementstyle=ConfineIn formatcopy=TRUE lockcomponents=FALSE outline 1852.41,-2940.95 1060.09,-2940.95 1060.09,-2552.17 1852.41,-2552.17
RoomDefinition PORTA [False] p2: confinementstyle=ConfineIn formatcopy=TRUE lockcomponents=FALSE outline 3702.81,-2940.95 2910.48,-2940.95 2910.48,-2552.17 3702.81,-2552.17
RoomDefinition MC2 [False] p3: confinementstyle=ConfineIn formatcopy=TRUE lockcomponents=FALSE outline 2905.51,-1240.16 5116.73,-1240.16 5116.73,-1611.8 2905.51,-1611.8
RoomDefinition PORTC [False] p4: confinementstyle=ConfineIn formatcopy=TRUE lockcomponents=FALSE outline 1454.72,2940.94 2247.05,2940.94 2247.05,2552.17 1454.72,2552.17
RoomDefinition PORTD [False] p5: confinementstyle=ConfineIn formatcopy=TRUE lockcomponents=FALSE outline 3305.12,2940.94 4097.44,2940.94 4097.44,2552.17 3305.12,2552.17
RoomDefinition MC1 [False] p6: confinementstyle=ConfineIn formatcopy=TRUE lockcomponents=FALSE outline 2905.51,1633.86 5116.73,1633.86 5116.73,1262.21 2905.51,1262.21
RoomDefinition M.2 [False vs False] p7: confinementstyle=ConfineIn formatcopy=TRUE lockcomponents=FALSE outline 5779.53,-204.72 6026.57,-204.72 6026.57,-801.18 5779.53,-801.18
RoomDefinition PORTF [False] p8: confinementstyle=ConfineIn formatcopy=TRUE lockcomponents=FALSE outline 7468.5,2929.13 8137.8,2929.13 8137.8,2578.74 7468.5,2578.74
RoomDefinition PORTE [False] p9: confinementstyle=ConfineIn formatcopy=TRUE lockcomponents=FALSE outline 5421.26,2929.13 6090.55,2929.13 6090.55,2578.74 5421.26,2578.74
RoomDefinition MC3 [False] p10: confinementstyle=ConfineIn formatcopy=TRUE lockcomponents=FALSE outline 5279.53,1169.9 5669.29,1169.9 5669.29,-1169.87 5279.53,-1169.87
RoomDefinition MC1A [False] p11: confinementstyle=ConfineIn formatcopy=TRUE lockcomponents=FALSE outline 3629.92,2216.54 4348.8,2216.54 4348.8,1972.44 3629.92,1972.44
RoutingLayers [All] p1: top layer_v5=TRUE mid layer 1_v5=TRUE mid layer 2_v5=TRUE mid layer 3_v5=TRUE mid layer 4_v5=TRUE mid layer 5_v5=TRUE mid layer 6_v5=FALSE bottom layer_v5=TRUE
RoutingVias [All] p1: holewidth=10 width=18 viastyle="Through Hole" minholewidth=10 minwidth=18 maxholewidth=50 maxwidth=100
SilkToSilkClearance [All] p1: silktosilkclearance=0.1
SilkToSolderMaskClearance SilkscreenOverComponentPads [IsPad] p1: minsilkscreentomaskgap=2 clearancetoexposedcopper=TRUE
SolderMaskExpansion [All] p1: expansion=2 istentingtop=FALSE
Width okWidth_50ohm [InNetClass('50ohm')] p1: maxlimit=4.6 minlimit=1 preferedwidth=1 toplayer_minwidth=4.5 toplayer_maxwidth=4.5 toplayer_prefwidth=4.5 midlayer1_maxwidth=1 midlayer2_minwidth=4.6 midlayer2_prefwidth=4.6 midlayer3_maxwidth=1 midlayer4_maxwidth=1 midlayer5_maxwidth=1 midlayer6_maxwidth=1 bottomlayer_minwidth=4.5 bottomlayer_maxwidth=4.5 bottomlayer_prefwidth=4.5 minimp=50.000000 maximp=50.000000 favimp=50.000000
Width Width_GPIO [InNetClass('GPIO_Space')] p2: maxlimit=5 minlimit=4 preferedwidth=5
Width okWidth [All] p3: maxlimit=150 minlimit=4 preferedwidth=6 minimp=50.000000 maximp=50.000000 favimp=50.000000
20 further rules are at their usual default settings.

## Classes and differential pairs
net class MC2B_2MM: MC2B_1 MC2B_2 MC2B_3 MC2B_4 MC2B_5 MC2B_6 MC2B_7 MC2B_8 MC2B_9 MC2B_10 MC2B_11 MC2B_12 MC2B_13 MC2B_14 MC2B_15 MC2B_16 MC2B_17 MC2B_18 MC2B_19 MC2B_20 MC2B_21 MC2B_22 MC2B_23 MC2B_24 MC2B_25 MC2B_26 MC2B_27 MC2B_28 MC2B_29 MC2B_30 MC2B_31 MC2B_32 MC2B_33 MC2B_34 MC2B_35 MC2B_36 MC2B_37 MC2B_38 MC2B_39 MC2B_40
net class GPIO_Space: I2C_SCL I2C_SDA M2_ALERT_B M2_ALERT_B_3V3 M2_CLKREQ_B M2_CLKREQ_B_3V3 M2_DEVSLP M2_DEVSLP_3V3 M2_LED_1_B M2_LED_1_B_3V3 M2_PEDET M2_PEDET_3V3 M2_PERST_B M2_PERST_B_3V3 M2_PEWAKE_B M2_PEWAKE_B_3V3 M2_SMB_CLK M2_SMB_CLK_1V8 M2_SMB_DATA M2_SMB_DATA_1V8 M2_SUSCLK M2_SUSCLK_3V3 M2_THREESTATE# M2_THREESTATE_N_IO QSFP_1_INT_B QSFP_1_INT_B_3V3 QSFP_1_LP_MODE QSFP_1_LP_MODE_3V3 QSFP_1_MODPRS_B QSFP_1_MODPRS_B_3V3 QSFP_1_MODSEL_B QSFP_1_MODSEL_B_3V3 QSFP_1_RESET_B QSFP_1_RESET_B_3V3 QSFP_1_SCL QSFP_1_SCL_3V3 QSFP_1_SDA QSFP_1_SDA_3V3 QSFP_2_INT_B QSFP_2_INT_B_3V3 QSFP_2_LP_MODE QSFP_2_LP_MODE_3V3 QSFP_2_MODPRS_B QSFP_2_MODPRS_B_3V3 QSFP_2_MODSEL_B QSFP_2_MODSEL_B_3V3 QSFP_2_RESET_B QSFP_2_RESET_B_3V3 QSFP_2_SCL QSFP_2_SCL_3V3 QSFP_2_SDA QSFP_2_SDA_3V3 QSFP_THREESTATE# QSFP_THREESTATE_N_IO
net class QSFP2_MGT: QSFP_2_RX1N QSFP_2_RX1P QSFP_2_RX2N QSFP_2_RX2P QSFP_2_RX3N QSFP_2_RX3P QSFP_2_RX4N QSFP_2_RX4P QSFP_2_TX1N QSFP_2_TX1P QSFP_2_TX2N QSFP_2_TX2P QSFP_2_TX3N QSFP_2_TX3P QSFP_2_TX4N QSFP_2_TX4P
net class SATA_MGT: SATA_1_RXB+ SATA_1_RXB+_C SATA_1_RXB- SATA_1_RXB-_C SATA_1_TXA+ SATA_1_TXA+_C SATA_1_TXA- SATA_1_TXA-_C SATA_2_RXB+ SATA_2_RXB+_C SATA_2_RXB- SATA_2_RXB-_C SATA_2_TXA+ SATA_2_TXA+_C SATA_2_TXA- SATA_2_TXA-_C
net class PORTF_MGT: PORTF_REFCLKN PORTF_REFCLKP PORTF_RX0N PORTF_RX0P PORTF_RX1N PORTF_RX1P PORTF_RX2N PORTF_RX2P PORTF_RX3N PORTF_RX3P PORTF_TX0N PORTF_TX0P PORTF_TX1N PORTF_TX1P PORTF_TX2N PORTF_TX2P PORTF_TX3N PORTF_TX3P
net class PORTE_MGT: PORTE_REFCLKN PORTE_REFCLKP PORTE_RX0N PORTE_RX0P PORTE_RX1N PORTE_RX1P PORTE_RX2N PORTE_RX2P PORTE_RX3N PORTE_RX3P PORTE_TX0N PORTE_TX0P PORTE_TX1N PORTE_TX1P PORTE_TX2N PORTE_TX2P PORTE_TX3N PORTE_TX3P
net class JTAG: JTAG_TCK JTAG_TDI JTAG_TDO JTAG_TMS
net class 50ohm: JTAG_TCK JTAG_TDI JTAG_TDO JTAG_TMS MC1A_3 MC1A_4 MC1A_5 MC1A_6 MC1A_7 MC1A_8 MC1A_9 MC1A_10 MC1A_11 MC1A_12 MC1A_13 MC1A_14 MC1A_15 MC1A_16 MC1A_17 MC1A_18 MC1A_19 MC1A_20 MC1A_21 MC1A_22 MC1A_23 MC1A_24 MC1A_25 MC1A_26 MC1A_27 MC1A_28 MC1A_29 MC1A_30 MC1A_31 MC1A_32 MC1A_33 MC1A_34 MC1A_35 MC1A_36 MC1A_37 MC1A_38 MC1A_39 MC1A_40 MC2A_1 MC2A_2 MC2A_3 MC2A_4 MC2A_5 MC2A_6 MC2A_7 MC2A_8 MC2A_9 MC2A_10 MC2A_11 MC2A_12 MC2A_13 MC2A_14 MC2A_15 MC2A_16 MC2A_17 MC2A_18 MC2A_19 MC2A_20 MC2A_21 MC2A_22 MC2A_23 MC2A_24 MC2A_25 MC2A_26 MC2A_27 MC2A_28 MC2A_29 MC2A_30 MC2A_31 MC2A_32 MC2A_33 MC2A_34 MC2A_35 MC2A_36 MC2A_37 MC2A_38 MC2A_39 MC2A_40 MC2B_1 MC2B_2 MC2B_3 MC2B_4 MC2B_5 MC2B_6 MC2B_7 MC2B_8 MC2B_9 MC2B_10 MC2B_11 MC2B_12 MC2B_13 MC2B_14 MC2B_15 MC2B_16 MC2B_17 MC2B_18 MC2B_19 MC2B_20 MC2B_21 MC2B_22 MC2B_23 MC2B_24 MC2B_25 MC2B_26 MC2B_27 MC2B_28 MC2B_29 MC2B_30 MC2B_31 MC2B_32 MC2B_33 MC2B_34 MC2B_35 MC2B_36 MC2B_37 MC2B_38 MC2B_39 MC2B_40 PORTA_S16 PORTA_S17 PORTA_S18 PORTA_S19 PORTA_S20 PORTA_S21 PORTA_S22 PORTA_S23 PORTA_S24 PORTA_S25 PORTA_S26 PORTA_S27 PORTB_S16 PORTB_S17 PORTB_S18 PORTB_S19 PORTB_S20 PORTB_S21 PORTB_S22 PORTB_S23 PORTB_S24 PORTB_S25 PORTB_S26 PORTB_S27 PORTC_S16 PORTC_S17 PORTC_S18 PORTC_S19 PORTC_S20 PORTC_S21 PORTC_S22 PORTC_S23 PORTC_S24 PORTC_S25 PORTC_S26 PORTC_S27 PORTD_S16 PORTD_S17 PORTD_S18 PORTD_S19 PORTD_S20 PORTD_S21 PORTD_S22 PORTD_S23 PORTD_S24 PORTD_S25 PORTD_S26 PORTD_S27 PORTE_S0 PORTE_S1 PORTE_S2 PORTE_S3 PORTE_S4 PORTE_S5 PORTE_S6 PORTE_S7 PORTE_S8 PORTE_S9 PORTF_S0 PORTF_S1 PORTF_S2 PORTF_S3 PORTF_S4 PORTF_S5 PORTF_S6 PORTF_S7 PORTF_S8 PORTF_S9
net class Power: +1.8VDD +3.3V_M.2 +3.3V_QSFP +3.3V_SZG +3.3VDD +5V_SZG +VDCIN VCCBATT VDDD VIO1 VIO2
net class U.FL_MGT: UFL_RXN0 UFL_RXN1 UFL_RXP0 UFL_RXP1 UFL_TXN0 UFL_TXN1 UFL_TXP0 UFL_TXP1
net class SMA_MGT: SMA_RXN0 SMA_RXN1 SMA_RXP0 SMA_RXP1 SMA_TXN0 SMA_TXN1 SMA_TXP0 SMA_TXP1
net class QSFP_CONTROL: QSFP_1_INT_B QSFP_1_INT_B_3V3 QSFP_1_LP_MODE QSFP_1_LP_MODE_3V3 QSFP_1_MODPRS_B QSFP_1_MODPRS_B_3V3 QSFP_1_MODSEL_B QSFP_1_MODSEL_B_3V3 QSFP_1_RESET_B QSFP_1_RESET_B_3V3 QSFP_1_SCL QSFP_1_SCL_3V3 QSFP_1_SDA QSFP_1_SDA_3V3 QSFP_2_INT_B QSFP_2_INT_B_3V3 QSFP_2_LP_MODE QSFP_2_LP_MODE_3V3 QSFP_2_MODPRS_B QSFP_2_MODPRS_B_3V3 QSFP_2_MODSEL_B QSFP_2_MODSEL_B_3V3 QSFP_2_RESET_B QSFP_2_RESET_B_3V3 QSFP_2_SCL QSFP_2_SCL_3V3 QSFP_2_SDA QSFP_2_SDA_3V3
net class QSFP1_MGT: QSFP_1_RX1N QSFP_1_RX1P QSFP_1_RX2N QSFP_1_RX2P QSFP_1_RX3N QSFP_1_RX3P QSFP_1_RX4N QSFP_1_RX4P QSFP_1_TX1N QSFP_1_TX1P QSFP_1_TX2N QSFP_1_TX2P QSFP_1_TX3N QSFP_1_TX3P QSFP_1_TX4N QSFP_1_TX4P
net class M2_MGT: M2_PER_N0 M2_PER_N1 M2_PER_N2 M2_PER_N3 M2_PER_P0 M2_PER_P1 M2_PER_P2 M2_PER_P3 M2_PET_N0 M2_PET_N0_C M2_PET_N1 M2_PET_N1_C M2_PET_N2 M2_PET_N2_C M2_PET_N3 M2_PET_N3_C M2_PET_P0 M2_PET_P0_C M2_PET_P1 M2_PET_P1_C M2_PET_P2 M2_PET_P2_C M2_PET_P3 M2_PET_P3_C
net class M2_CONTROL: M2_ALERT_B M2_ALERT_B_3V3 M2_CLKREQ_B M2_CLKREQ_B_3V3 M2_DEVSLP M2_DEVSLP_3V3 M2_LED_1_B M2_LED_1_B_3V3 M2_PEDET M2_PEDET_3V3 M2_PERST_B M2_PERST_B_3V3 M2_PEWAKE_B M2_PEWAKE_B_3V3 M2_SMB_CLK M2_SMB_CLK_1V8 M2_SMB_DATA M2_SMB_DATA_1V8 M2_SUSCLK M2_SUSCLK_3V3
net class MC2A_2MM: MC2A_1 MC2A_2 MC2A_3 MC2A_4 MC2A_5 MC2A_6 MC2A_7 MC2A_8 MC2A_9 MC2A_10 MC2A_11 MC2A_12 MC2A_13 MC2A_14 MC2A_15 MC2A_16 MC2A_17 MC2A_18 MC2A_19 MC2A_20 MC2A_21 MC2A_22 MC2A_23 MC2A_24 MC2A_25 MC2A_26 MC2A_27 MC2A_28 MC2A_29 MC2A_30 MC2A_31 MC2A_32 MC2A_33 MC2A_34 MC2A_35 MC2A_36 MC2A_37 MC2A_38 MC2A_39 MC2A_40
net class MC1A_2MM: MC1A_3 MC1A_4 MC1A_5 MC1A_6 MC1A_7 MC1A_8 MC1A_9 MC1A_10 MC1A_11 MC1A_12 MC1A_13 MC1A_14 MC1A_15 MC1A_16 MC1A_17 MC1A_18 MC1A_19 MC1A_20 MC1A_21 MC1A_22 MC1A_23 MC1A_24 MC1A_25 MC1A_26 MC1A_27 MC1A_28 MC1A_29 MC1A_30 MC1A_31 MC1A_32 MC1A_33 MC1A_34 MC1A_35 MC1A_36 MC1A_37 MC1A_38 MC1A_39 MC1A_40 XADC_VN XADC_VP
net class PORTB: PORTB_C2P_CLKN PORTB_C2P_CLKP PORTB_P2C_CLKN PORTB_P2C_CLKP PORTB_S0_D0P PORTB_S1_D1P PORTB_S2_D0N PORTB_S3_D1N PORTB_S4_D2P PORTB_S5_D3P PORTB_S6_D2N PORTB_S7_D3N PORTB_S8_D4P PORTB_S9_D5P PORTB_S10_D4N PORTB_S11_D5N PORTB_S12_D6P PORTB_S13_D7P PORTB_S14_D6N PORTB_S15_D7N PORTB_S16 PORTB_S17 PORTB_S18 PORTB_S19 PORTB_S20 PORTB_S21 PORTB_S22 PORTB_S23 PORTB_S24 PORTB_S25 PORTB_S26 PORTB_S27
net class PORTA: PORTA_C2P_CLKN PORTA_C2P_CLKP PORTA_P2C_CLKN PORTA_P2C_CLKP PORTA_S0_D0P PORTA_S1_D1P PORTA_S2_D0N PORTA_S3_D1N PORTA_S4_D2P PORTA_S5_D3P PORTA_S6_D2N PORTA_S7_D3N PORTA_S8_D4P PORTA_S9_D5P PORTA_S10_D4N PORTA_S11_D5N PORTA_S12_D6P PORTA_S13_D7P PORTA_S14_D6N PORTA_S15_D7N PORTA_S16 PORTA_S17 PORTA_S18 PORTA_S19 PORTA_S20 PORTA_S21 PORTA_S22 PORTA_S23 PORTA_S24 PORTA_S25 PORTA_S26 PORTA_S27
net class PORTF: PORTF_C2P_CLKN PORTF_C2P_CLKP PORTF_P2C_CLKN PORTF_P2C_CLKP PORTF_S0 PORTF_S1 PORTF_S2 PORTF_S3 PORTF_S4 PORTF_S5 PORTF_S6 PORTF_S7 PORTF_S8 PORTF_S9
net class PORTC: PORTC_C2P_CLKN PORTC_C2P_CLKP PORTC_P2C_CLKN PORTC_P2C_CLKP PORTC_S0_D0P PORTC_S1_D1P PORTC_S2_D0N PORTC_S3_D1N PORTC_S4_D2P PORTC_S5_D3P PORTC_S6_D2N PORTC_S7_D3N PORTC_S8_D4P PORTC_S9_D5P PORTC_S10_D4N PORTC_S11_D5N PORTC_S12_D6P PORTC_S13_D7P PORTC_S14_D6N PORTC_S15_D7N PORTC_S16 PORTC_S17 PORTC_S18 PORTC_S19 PORTC_S20 PORTC_S21 PORTC_S22 PORTC_S23 PORTC_S24 PORTC_S25 PORTC_S26 PORTC_S27
net class PORTD: PORTD_C2P_CLKN PORTD_C2P_CLKP PORTD_P2C_CLKN PORTD_P2C_CLKP PORTD_S0_D0P PORTD_S1_D1P PORTD_S2_D0N PORTD_S3_D1N PORTD_S4_D2P PORTD_S5_D3P PORTD_S6_D2N PORTD_S7_D3N PORTD_S8_D4P PORTD_S9_D5P PORTD_S10_D4N PORTD_S11_D5N PORTD_S12_D6P PORTD_S13_D7P PORTD_S14_D6N PORTD_S15_D7N PORTD_S16 PORTD_S17 PORTD_S18 PORTD_S19 PORTD_S20 PORTD_S21 PORTD_S22 PORTD_S23 PORTD_S24 PORTD_S25 PORTD_S26 PORTD_S27
net class PORTE: PORTE_C2P_CLKN PORTE_C2P_CLKP PORTE_P2C_CLKN PORTE_P2C_CLKP PORTE_S0 PORTE_S1 PORTE_S2 PORTE_S3 PORTE_S4 PORTE_S5 PORTE_S6 PORTE_S7 PORTE_S8 PORTE_S9
differential pair class 100ohm_Diff: DP_100MHZ_OSC_ DP_100MHZ_REFCLK DP_200MHZ_OSC DP_M2_PER_0 DP_M2_PER_1 DP_M2_PER_2 DP_M2_PER_3 DP_M2_PET_0 DP_M2_PET_0_C DP_M2_PET_1 DP_M2_PET_1_C DP_M2_PET_2 DP_M2_PET_2_C DP_M2_PET_3 DP_M2_PET_3_C DP_M2_REFCLK DP_M2_REFCLK_ DP_PORTA_C2P_CLK DP_PORTA_D0 DP_PORTA_D1 DP_PORTA_D2 DP_PORTA_D3 DP_PORTA_D4 DP_PORTA_D5 DP_PORTA_D6 DP_PORTA_D7 DP_PORTA_P2C_CLK DP_PORTB_C2P_CLK DP_PORTB_D0 DP_PORTB_D1 DP_PORTB_D2 DP_PORTB_D3 DP_PORTB_D4 DP_PORTB_D5 DP_PORTB_D6 DP_PORTB_D7 DP_PORTB_P2C_CLK DP_PORTC_C2P_CLK DP_PORTC_D0 DP_PORTC_D1 DP_PORTC_D2 DP_PORTC_D3 DP_PORTC_D4 DP_PORTC_D5 DP_PORTC_D6 DP_PORTC_D7 DP_PORTC_P2C_CLK DP_PORTD_C2P_CLK DP_PORTD_D0 DP_PORTD_D1 DP_PORTD_D2 DP_PORTD_D3 DP_PORTD_D4 DP_PORTD_D5 DP_PORTD_D6 DP_PORTD_D7 DP_PORTD_P2C_CLK DP_PORTE_C2P DP_PORTE_P2C DP_PORTE_REFCLK DP_PORTE_RX0 DP_PORTE_RX1 DP_PORTE_RX2 DP_PORTE_RX3 DP_PORTE_TX0 DP_PORTE_TX1 DP_PORTE_TX2 DP_PORTE_TX3 DP_PORTF_C2P DP_PORTF_C2P_CLK DP_PORTF_P2C DP_PORTF_P2C_CLK DP_PORTF_REFCLK DP_PORTF_RX0 DP_PORTF_RX1 DP_PORTF_RX2 DP_PORTF_RX3 DP_PORTF_TX0 DP_PORTF_TX1 DP_PORTF_TX2 DP_PORTF_TX3 DP_QSFP_1_RX1 DP_QSFP_1_RX2 DP_QSFP_1_RX3 DP_QSFP_1_RX4 DP_QSFP_1_TX1 DP_QSFP_1_TX2 DP_QSFP_1_TX3 DP_QSFP_1_TX4 DP_QSFP_2_RX1 DP_QSFP_2_RX2 DP_QSFP_2_RX3 DP_QSFP_2_RX4 DP_QSFP_2_TX1 DP_QSFP_2_TX2 DP_QSFP_2_TX3 DP_QSFP_2_TX4 DP_RX0 DP_RX1 DP_RX2 DP_RX3 DP_SATA_1_TXA DP_SATA_1_TXA_C DP_SATA_1_TXB DP_SATA_1_TXB_C DP_SATA_2_TXA DP_SATA_2_TXA_C DP_SATA_2_TXB DP_SATA_2_TXB_C DP_SMA_REFCLK DP_SMA_RX0 DP_SMA_RX1 DP_SMA_RX2 DP_SMA_RX3 DP_SMA_TX0 DP_SMA_TX1 DP_SMA_TX2 DP_SMA_TX3 DP_TX0 DP_TX1 DP_TX2 DP_TX3 DP_UFL_C_RX0 DP_UFL_C_RX1 DP_UFL_C_TX0 DP_UFL_C_TX1 DP_UFL_RX0 DP_UFL_RX1 DP_UFL_TX0 DP_UFL_TX1 DP_XADC_V
differential pair DP_PORTF_P2C: +PORTF_P2C_CLKP -PORTF_P2C_CLKN
differential pair DP_PORTE_P2C: +PORTE_P2C_CLKP -PORTE_P2C_CLKN
differential pair DP_PORTF_C2P: +PORTF_C2P_CLKP -PORTF_C2P_CLKN
differential pair DP_PORTE_C2P: +PORTE_C2P_CLKP -PORTE_C2P_CLKN
differential pair DP_M2_REFCLK_: +M2_REFCLK_P -M2_REFCLK_N
differential pair DP_100MHZ_OSC_: +100MHZ_OSC_P -100MHZ_OSC_N
differential pair DP_SMA_TX1: +SMA_TXP1 -SMA_TXN1
differential pair DP_UFL_RX0: +UFL_RXP0 -UFL_RXN0
differential pair DP_UFL_RX1: +UFL_RXP1 -UFL_RXN1
differential pair DP_UFL_TX0: +UFL_TXP0 -UFL_TXN0
differential pair DP_UFL_TX1: +UFL_TXP1 -UFL_TXN1
differential pair DP_UFL_C_RX1: +NetC18_1 -NetC20_1
differential pair DP_UFL_C_TX1: +NetC19_1 -NetC21_1
differential pair DP_UFL_C_RX0: +NetC14_1 -NetC16_1
differential pair DP_UFL_C_TX0: +NetC15_1 -NetC17_1
differential pair DP_SMA_RX3: +NetC10_1 -NetC12_1
differential pair DP_SMA_TX3: +NetC11_1 -NetC13_1
differential pair DP_SMA_RX2: +NetC6_1 -NetC8_1
differential pair DP_SMA_TX2: +NetC7_1 -NetC9_1
differential pair DP_PORTE_TX3: +PORTE_TX3P -PORTE_TX3N
differential pair DP_PORTE_TX2: +PORTE_TX2P -PORTE_TX2N
differential pair DP_PORTE_RX3: +PORTE_RX3P -PORTE_RX3N
differential pair DP_PORTE_RX2: +PORTE_RX2P -PORTE_RX2N
differential pair DP_PORTF_TX3: +PORTF_TX3P -PORTF_TX3N
differential pair DP_PORTF_TX2: +PORTF_TX2P -PORTF_TX2N
differential pair DP_PORTF_RX3: +PORTF_RX3P -PORTF_RX3N
differential pair DP_PORTF_RX2: +PORTF_RX2P -PORTF_RX2N
differential pair DP_TX3: +"" -""
differential pair DP_TX2: +"" -""
differential pair DP_TX1: +"" -""
differential pair DP_TX0: +"" -""
differential pair DP_RX3: +"" -""
differential pair DP_RX2: +"" -""
differential pair DP_RX1: +"" -""
differential pair DP_RX0: +"" -""
differential pair DP_200MHZ_OSC: +100MHZ_OSC_P -100MHZ_OSC_N
differential pair DP_M2_REFCLK: +M2_REFCLK_P -M2_REFCLK_N
differential pair DP_SATA_2_TXB_C: +SATA_2_RXB+_C -SATA_2_RXB-_C
differential pair DP_SATA_2_TXB: +SATA_2_RXB+ -SATA_2_RXB-
differential pair DP_SATA_2_TXA_C: +SATA_2_TXA+_C -SATA_2_TXA-_C
differential pair DP_SATA_2_TXA: +SATA_2_TXA+ -SATA_2_TXA-
differential pair DP_SATA_1_TXB: +SATA_1_RXB+ -SATA_1_RXB-
differential pair DP_SATA_1_TXB_C: +SATA_1_RXB+_C -SATA_1_RXB-_C
differential pair DP_SATA_1_TXA_C: +SATA_1_TXA+_C -SATA_1_TXA-_C
differential pair DP_SATA_1_TXA: +SATA_1_TXA+ -SATA_1_TXA-
differential pair DP_SMA_RX1: +SMA_RXP1 -SMA_RXN1
differential pair DP_SMA_RX0: +SMA_RXP0 -SMA_RXN0
differential pair DP_SMA_REFCLK: +"" -""
differential pair DP_SMA_TX0: +SMA_TXP0 -SMA_TXN0
differential pair DP_XADC_V: +XADC_VP -XADC_VN
differential pair DP_QSFP_2_TX4: +QSFP_2_TX4P -QSFP_2_TX4N
differential pair DP_QSFP_2_TX3: +QSFP_2_TX3P -QSFP_2_TX3N
differential pair DP_QSFP_2_TX2: +QSFP_2_TX2P -QSFP_2_TX2N
differential pair DP_QSFP_2_TX1: +QSFP_2_TX1P -QSFP_2_TX1N
differential pair DP_QSFP_2_RX4: +QSFP_2_RX4P -QSFP_2_RX4N
differential pair DP_QSFP_2_RX3: +QSFP_2_RX3P -QSFP_2_RX3N
differential pair DP_QSFP_2_RX2: +QSFP_2_RX2P -QSFP_2_RX2N
differential pair DP_QSFP_2_RX1: +QSFP_2_RX1P -QSFP_2_RX1N
differential pair DP_QSFP_1_TX4: +QSFP_1_TX4P -QSFP_1_TX4N
differential pair DP_QSFP_1_TX3: +QSFP_1_TX3P -QSFP_1_TX3N
differential pair DP_QSFP_1_TX2: +QSFP_1_TX2P -QSFP_1_TX2N
differential pair DP_QSFP_1_TX1: +QSFP_1_TX1P -QSFP_1_TX1N
differential pair DP_QSFP_1_RX4: +QSFP_1_RX4P -QSFP_1_RX4N
differential pair DP_QSFP_1_RX3: +QSFP_1_RX3P -QSFP_1_RX3N
differential pair DP_QSFP_1_RX2: +QSFP_1_RX2P -QSFP_1_RX2N
differential pair DP_QSFP_1_RX1: +QSFP_1_RX1P -QSFP_1_RX1N
differential pair DP_M2_PET_3_C: +M2_PET_P3_C -M2_PET_N3_C
differential pair DP_M2_PET_2_C: +M2_PET_P2_C -M2_PET_N2_C
differential pair DP_M2_PET_1_C: +M2_PET_P1_C -M2_PET_N1_C
differential pair DP_M2_PET_0_C: +M2_PET_P0_C -M2_PET_N0_C
differential pair DP_M2_PET_3: +M2_PET_P3 -M2_PET_N3
differential pair DP_M2_PET_2: +M2_PET_P2 -M2_PET_N2
differential pair DP_M2_PET_1: +M2_PET_P1 -M2_PET_N1
differential pair DP_M2_PET_0: +M2_PET_P0 -M2_PET_N0
differential pair DP_M2_PER_3: +M2_PER_P3 -M2_PER_N3
differential pair DP_M2_PER_2: +M2_PER_P2 -M2_PER_N2
differential pair DP_M2_PER_1: +M2_PER_P1 -M2_PER_N1
differential pair DP_M2_PER_0: +M2_PER_P0 -M2_PER_N0
differential pair DP_PORTF_TX1: +PORTF_TX1P -PORTF_TX1N
differential pair DP_PORTF_TX0: +PORTF_TX0P -PORTF_TX0N
differential pair DP_PORTF_RX1: +PORTF_RX1P -PORTF_RX1N
differential pair DP_PORTF_RX0: +PORTF_RX0P -PORTF_RX0N
differential pair DP_PORTF_REFCLK: +PORTF_REFCLKP -PORTF_REFCLKN
differential pair DP_PORTF_P2C_CLK: +PORTE_P2C_CLKP -PORTE_P2C_CLKN
differential pair DP_PORTF_C2P_CLK: +PORTE_C2P_CLKP -PORTE_C2P_CLKN
differential pair DP_PORTE_TX1: +PORTE_TX1P -PORTE_TX1N
differential pair DP_PORTE_TX0: +PORTE_TX0P -PORTE_TX0N
differential pair DP_PORTE_RX1: +PORTE_RX1P -PORTE_RX1N
differential pair DP_PORTE_RX0: +PORTE_RX0P -PORTE_RX0N
differential pair DP_PORTE_REFCLK: +PORTE_REFCLKP -PORTE_REFCLKN
differential pair DP_PORTD_D7: +PORTA_S13_D7P -PORTA_S15_D7N
differential pair DP_PORTD_D6: +PORTA_S12_D6P -PORTA_S14_D6N
differential pair DP_PORTD_D5: +PORTA_S9_D5P -PORTA_S11_D5N
differential pair DP_PORTD_D4: +PORTA_S8_D4P -PORTA_S10_D4N
differential pair DP_PORTD_D3: +PORTA_S5_D3P -PORTA_S7_D3N
differential pair DP_PORTD_D2: +PORTA_S4_D2P -PORTA_S6_D2N
differential pair DP_PORTD_D1: +PORTA_S1_D1P -PORTA_S3_D1N
differential pair DP_PORTD_D0: +PORTA_S0_D0P -PORTA_S2_D0N
differential pair DP_PORTD_P2C_CLK: +PORTA_P2C_CLKP -PORTA_P2C_CLKN
differential pair DP_PORTD_C2P_CLK: +PORTA_C2P_CLKP -PORTA_C2P_CLKN
differential pair DP_PORTC_D7: +PORTB_S13_D7P -PORTB_S15_D7N
differential pair DP_PORTC_D6: +PORTB_S12_D6P -PORTB_S14_D6N
differential pair DP_PORTC_D5: +PORTB_S9_D5P -PORTB_S11_D5N
differential pair DP_PORTC_D4: +PORTB_S8_D4P -PORTB_S10_D4N
differential pair DP_PORTC_D3: +PORTB_S5_D3P -PORTB_S7_D3N
differential pair DP_PORTC_D2: +PORTB_S4_D2P -PORTB_S6_D2N
differential pair DP_PORTC_D1: +PORTB_S1_D1P -PORTB_S3_D1N
differential pair DP_PORTC_D0: +PORTB_S0_D0P -PORTB_S2_D0N
differential pair DP_PORTC_P2C_CLK: +PORTB_P2C_CLKP -PORTB_P2C_CLKN
differential pair DP_PORTC_C2P_CLK: +PORTB_C2P_CLKP -PORTB_C2P_CLKN
differential pair DP_PORTB_D7: +PORTD_S13_D7P -PORTD_S15_D7N
differential pair DP_PORTB_D6: +PORTD_S12_D6P -PORTD_S14_D6N
differential pair DP_PORTB_D5: +PORTD_S9_D5P -PORTD_S11_D5N
differential pair DP_PORTB_D4: +PORTD_S8_D4P -PORTD_S10_D4N
differential pair DP_PORTB_D3: +PORTD_S5_D3P -PORTD_S7_D3N
differential pair DP_PORTB_D2: +PORTD_S4_D2P -PORTD_S6_D2N
differential pair DP_PORTB_D1: +PORTD_S1_D1P -PORTD_S3_D1N
differential pair DP_PORTB_D0: +PORTD_S0_D0P -PORTD_S2_D0N
differential pair DP_PORTB_P2C_CLK: +PORTD_P2C_CLKP -PORTD_P2C_CLKN
differential pair DP_PORTB_C2P_CLK: +PORTD_C2P_CLKP -PORTD_C2P_CLKN
differential pair DP_PORTA_D7: +PORTC_S13_D7P -PORTC_S15_D7N
differential pair DP_PORTA_D6: +PORTC_S12_D6P -PORTC_S14_D6N
differential pair DP_PORTA_D5: +PORTC_S9_D5P -PORTC_S11_D5N
differential pair DP_PORTA_D4: +PORTC_S8_D4P -PORTC_S10_D4N
differential pair DP_PORTA_D3: +PORTC_S5_D3P -PORTC_S7_D3N
differential pair DP_PORTA_D2: +PORTC_S4_D2P -PORTC_S6_D2N
differential pair DP_PORTA_D1: +PORTC_S1_D1P -PORTC_S3_D1N
differential pair DP_PORTA_D0: +PORTC_S0_D0P -PORTC_S2_D0N
differential pair DP_PORTA_P2C_CLK: +PORTC_P2C_CLKP -PORTC_P2C_CLKN
differential pair DP_PORTA_C2P_CLK: +PORTC_C2P_CLKP -PORTC_C2P_CLKN
differential pair DP_100MHZ_REFCLK: +"100MHZ _REFCLK_P" -100MHZ_REFCLK_N

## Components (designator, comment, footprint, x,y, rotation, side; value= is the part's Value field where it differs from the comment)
*1 "Opal Kelly Logo" okLogo-23x5-2021 4672.49,-1934.31 r0 top
C1 "SM-0402, 10%, 10v" CAPC1005X06A#1 125.29,-2566.93 r180 top value="0.1 u"
C2 "SM-0402, 10%, 10v" CAPC1005X06A#1 1881.89,1724.41 r180 top value="0.1 u"
C3 "C0402C104K8PACTU" CAPC1005X06A#2 9049.21,2440.94 r90 top value="0.1 u"
C4 "C0402C103K4RACTU" CAPC1005X06A#1 6027.56,-954.72 r270 top value="0.01 u"
C5 "C0402C104K8PACTU" CAPC1005X06A#2 9049.21,2362.2 r270 top value="0.1 u"
C6 "SM-0402, 10%, 10v" CAPC1005X06A#1 7344.78,-1446.08 r180 top value="0.1 u"
C7 "SM-0402, 10%, 10v" CAPC1005X06A#1 7934.16,-1444.91 r180 top value="0.1 u"
C8 "SM-0402, 10%, 10v" CAPC1005X06A#1 7344.78,-1485.08 r180 top value="0.1 u"
C9 "SM-0402, 10%, 10v" CAPC1005X06A#1 7934.16,-1483.91 r180 top value="0.1 u"
C10 "SM-0402, 10%, 10v" CAPC1005X06A#1 8526.26,-1443.91 r180 top value="0.1 u"
C11 "SM-0402, 10%, 10v" CAPC1005X06A#1 9117.89,-1444.91 r180 top value="0.1 u"
C12 "SM-0402, 10%, 10v" CAPC1005X06A#1 8526.26,-1482.91 r180 top value="0.1 u"
C13 "SM-0402, 10%, 10v" CAPC1005X06A#1 9117.89,-1483.91 r180 top value="0.1 u"
C14 "SM-0402, 10%, 10v" CAPC1005X06A#1 8785.4,-2261.16 r90 top value="0.1 u"
C15 "SM-0402, 10%, 10v" CAPC1005X06A#1 8077.74,-2301.32 r270 top value="0.1 u"
C16 "SM-0402, 10%, 10v" CAPC1005X06A#1 8746.03,-2261.16 r90 top value="0.1 u"
C17 "SM-0402, 10%, 10v" CAPC1005X06A#1 8038.37,-2301.32 r270 top value="0.1 u"
C18 "SM-0402, 10%, 10v" CAPC1005X06A#1 8786.4,-2694.23 r90 top value="0.1 u"
C19 "SM-0402, 10%, 10v" CAPC1005X06A#1 8076.74,-2734.39 r270 top value="0.1 u"
C20 "SM-0402, 10%, 10v" CAPC1005X06A#1 8747.03,-2694.23 r90 top value="0.1 u"
C21 "SM-0402, 10%, 10v" CAPC1005X06A#1 8037.37,-2734.39 r270 top value="0.1 u"
C22 "SM-0402, 10%, 10v" CAPC1005X06A#1 6771.74,-1036.13 r90 top value="0.1 u"
C23 "SM-0402, 10%, 10v" CAPC1005X06A#1 6575.01,-1547.24 r90 top value="0.1 u"
C24 "SM-0402, 10%, 10v" CAPC1005X06A#1 6736.43,-1036.13 r90 top value="0.1 u"
C25 "SM-0402, 10%, 10v" CAPC1005X06A#1 6610.45,-1547.24 r90 top value="0.1 u"
C26 "SM-0402, 10%, 10v" CAPC1005X06A#1 6468.5,-1036.13 r90 top value="0.1 u"
C27 "SM-0402, 10%, 10v" CAPC1005X06A#1 6725.01,-1547.24 r90 top value="0.1 u"
C28 "SM-0402, 10%, 10v" CAPC1005X06A#1 6503.94,-1036.13 r90 top value="0.1 u"
C29 "SM-0402, 10%, 10v" CAPC1005X06A#1 6760.45,-1547.24 r90 top value="0.1 u"
C30 "LMK107BJ106MALTD" CAPC1608N 1252.74,-1849.66 r270 top value=10u
C31 "JMK105BBJ475MV-F" CAPC1005X06A#1 1202.74,-1870.66 r270 top value=4.7u
C32 "C1005X5R1A335K050BC" CAPC1005X06A#1 1162.74,-1846.66 r270 top value=3.3u
C33 "C3216X5R1V226M160AC" CAPC3216N 1098.1,-1770.16 r90 top value="22 u"
C34 "TMK105BJ104KV-F" CAPC1005X06A#1 1101.1,-1892.66 r180 top value="0.1 u"
C35 "C0402C104K8PACTU" CAPC1005X06A#1 1450.47,-2230.58 r90 top value="0.1 u"
C36 "EEE-FK1E221P" CAPAE9083X70N 948.82,1976.38 r270 top value=220u
C37 "TMK105BJ104KV-F" CAPC1005X06A#1 870.08,2492.13 r180 top value="0.1 u"
C38 "C0402C104K8PACTU" CAPC1005X06A#1 1805.27,-2135.66 r270 top value="0.1 u"
C39 "LMK316AB7226KL-TR" CAPC3216N 1872.27,-2162.66 r270 top value=22u
C40 "LMK316AB7226KL-TR" CAPC3216N 1963.1,-2162.66 r270 top value=22u
C41 "SM-0402, 5%, 50v" CAPC1005X06A#1 1393.47,-2276.3 r270 top value="56 p"
C42 "C0402C472K5RACTU" CAPC1005X06A#1 1256.74,-2345.66 r180 top value="4.7 n"
C43 "C0402C104K8PACTU" CAPC1005X06A#1 1237.84,-2292.66 r270 top value="0.1 u"
C44 "C0402C220J5GACTU" CAPC1005X06A#1 1333.74,-2345.66 r0 top value="22 p"
C45 "C0402C104K8PACTU" CAPC1005X06A#1 1462.74,-1938.66 r270 top value="0.1 u"
C46 "C3216X5R1V226M160AC" CAPC3216N 1456.74,-2082.66 r90 top value="22 u"
C47 "TMK105BJ104KV-F" CAPC1005X06A#1 1390.47,-2082.58 r90 top value="0.1 u"
C48 "C0402C104K8PACTU" CAPC1005X06A#1 1805.27,-2003.66 r90 top value="0.1 u"
C49 "LMK316AB7226KL-TR" CAPC3216N 1872.57,-1977.24 r90 top value=22u
C50 "LMK316AB7226KL-TR" CAPC3216N 1963.1,-1977.24 r90 top value=22u
C51 "C0402C104K8PACTU" CAPC1005X06A#1 1302.74,-1871.66 r270 top value="0.1 u"
C52 "SM-0402, 5%, 50v" CAPC1005X06A#1 1462.74,-1863.66 r90 top value="56 p"
C53 "C0402C472K5RACTU" CAPC1005X06A#1 1303.27,-1796.66 r90 top value="4.7 n"
C54 "C0402C220J5GACTU" CAPC1005X06A#1 1342.74,-1796.66 r90 top value="22 p"
C55 "C0402C104K8PACTU" CAPC1005X06A#1 1033.1,-1753.07 r90 top value="0.1 u"
C56 "C0402C104K8PACTU" CAPC1005X06A#1 927.74,-1977.66 r270 top value="0.1 u"
C57 "C3216X5R1V226M160AC" CAPC3216N 924.66,-2100.66 r180 top value="22 u"
C58 "TMK105BJ104KV-F" CAPC1005X06A#1 977.38,-2035.58 r180 top value="0.1 u"
C59 "C0402C104K8PACTU" CAPC1005X06A#1 680.32,-1997.43 r90 top value="0.1 u"
C60 "LMK316AB7226KL-TR" CAPC3216N 614.32,-1972.43 r90 top value=22u
C61 "LMK316AB7226KL-TR" CAPC3216N 524.14,-1972.43 r90 top value=22u
C62 "C0402C560J5GACTU" CAPC1005X06A#1 960.74,-1902.66 r90 top value="56 p"
C63 "C0402C104K8PACTU" CAPC1005X06A#1 1085.74,-2276.16 r270 top value="0.1 u"
C64 "C0402C472K5RACTU" CAPC1005X06A#1 993.74,-1828.66 r90 top value="4.7 n"
C65 "C0402C220J5GACTU" CAPC1005X06A#1 1033.74,-1829.66 r90 top value="22 p"
C66 "C0402C104K8PACTU" CAPC1005X06A#1 927.74,-2183.66 r90 top value="0.1 u"
C67 "C0402C104K8PACTU" CAPC1005X06A#1 680.32,-2132.54 r270 top value="0.1 u"
C68 "LMK316AB7226KL-TR" CAPC3216N 614.32,-2158.54 r270 top value=22u
C69 "LMK316AB7226KL-TR" CAPC3216N 524.14,-2158.54 r270 top value=22u
C70 "C0402C560J5GACTU" CAPC1005X06A#1 967.74,-2256.38 r270 top value="56 p"
C71 "SM-0402, 5%, 50V, NP0" CAPC1005X06A#1 1160.74,-2350.16 r90 top value="100 p"
C72 "C0402C472K5RACTU" CAPC1005X06A#1 1045.74,-2346.66 r270 top value="4.7 n"
C73 "GJM1555C1H5R0CB01D" CAPC1005X06A#1 1198.74,-2327.16 r90 top value="5 p"
C74 "C0402C220J5GACTU" CAPC1005X06A#1 1005.74,-2346.77 r270 top value="22 p"
C75 "C0402C104K8PACTU" CAPC1005X06A#1 5787.4,-1196.85 r0 top value="0.1 u"
C76 "C0402C104K8PACTU" CAPC1005X06A#1 6165.35,-1196.85 r180 top value="0.1 u"
C77 "SM-0402, 10%, 10V, X5R" CAPC1005X06A#1 5862.61,-712.6 r0 top value="0.22 u"
C78 "SM-0402, 10%, 10V, X5R" CAPC1005X06A#1 5862.61,-673.23 r0 top value="0.22 u"
C79 "SM-0402, 10%, 10V, X5R" CAPC1005X06A#1 5862.61,-594.01 r0 top value="0.22 u"
C80 "SM-0402, 10%, 10V, X5R" CAPC1005X06A#1 5862.61,-555.01 r0 top value="0.22 u"
C81 "SM-0402, 10%, 10V, X5R" CAPC1005X06A#1 5862.61,-476.38 r0 top value="0.22 u"
C82 "SM-0402, 10%, 10V, X5R" CAPC1005X06A#1 5862.61,-437.01 r0 top value="0.22 u"
C83 "SM-0402, 10%, 10V, X5R" CAPC1005X06A#1 5862.61,-358.01 r0 top value="0.22 u"
C84 "SM-0402, 10%, 10V, X5R" CAPC1005X06A#1 5862.61,-318.9 r0 top value="0.22 u"
C85 "LMK105BJ105KV-F" CAPC1005X06A#1 6165.35,-1161.42 r180 top value=1u
C86 "C0402C104K8PACTU" CAPC1005X06A#1 5791.34,-1452.76 r90 top value="0.1 u"
C87 "C0402C104K8PACTU" CAPC1005X06A#2 8082.42,2219.65 r180 top value="0.1 u"
C88 "C0402C103K4RACTU" CAPC1005X06A#1 5810.1,-1082.14 r90 top value="0.01 u"
C89 "C0402C104K8PACTU" CAPC1005X06A#2 8275.33,2219.65 r180 top value="0.1 u"
C90 "SM-0402, 10%, 10v" CAPC1005X06A#1 6761.8,920.17 r0 top value="0.1 u"
C91 "SM-1206, 10%, 10v, X7R" CAPC3216N 6805.1,800.09 r90 top value=22u
C92 "SM-0402, 10%, 10v" CAPC1005X06A#1 6506.09,920.17 r0 top value="0.1 u"
C93 "SM-1206, 10%, 10v, X7R" CAPC3216N 6523.61,800.09 r90 top value=22u
C94 "SM-1206, 10%, 10v, X7R" CAPC3216N 6666.32,800.09 r90 top value=22u
C95 "SM-0402, 10%, 10v" CAPC1005X06A#1 6623.02,920.17 r0 top value="0.1 u"
C96 "LMK105BJ105KV-F" CAPC1005X06A#1 8196.59,2219.65 r0 top value=1u
C97 "C0402C104K8PACTU" CAPC1005X06A#1 8529.29,2220.58 r180 top value="0.1 u"
C98 "C0402C104K8PACTU" CAPC1005X06A#1 8726.14,2220.58 r180 top value="0.1 u"
C99 "LMK105BJ105KV-F" CAPC1005X06A#1 8647.4,2220.58 r0 top value=1u
C100 "C0402C104K8PACTU" CAPC1005X06A#1 9053.15,2204.72 r90 top value="0.1 u"
C101 "C0402C104K8PACTU" CAPC1005X06A#1 9053.15,2125.98 r270 top value="0.1 u"
C102 "SM-0402, 10%, 10v" CAPC1005X06A#1 6761.78,1943.8 r0 top value="0.1 u"
C103 "SM-1206, 10%, 10v, X7R" CAPC3216N 6805.09,1823.72 r90 top value=22u
C104 "SM-0402, 10%, 10v" CAPC1005X06A#1 6506.08,1943.8 r0 top value="0.1 u"
C105 "SM-1206, 10%, 10v, X7R" CAPC3216N 6523.59,1823.72 r90 top value=22u
C106 "SM-1206, 10%, 10v, X7R" CAPC3216N 6666.31,1823.72 r90 top value=22u
C107 "SM-0402, 10%, 10v" CAPC1005X06A#1 6623,1943.8 r0 top value="0.1 u"
C108 "C0402C104K8PACTU" CAPC1005X06A#1 7684.78,2219.62 r180 top value="0.1 u"
C109 "C0402C104K8PACTU" CAPC1005X06A#1 7877.69,2219.62 r180 top value="0.1 u"
C110 "LMK105BJ105KV-F" CAPC1005X06A#2 7798.95,2219.62 r0 top value=1u
C111 "SM-1206, 10%, 10v, X7R" CAPC3216N 6569.87,1128.83 r0 top value=22u
C112 "SM-0402, 10%, 10v" CAPC1005X06A#2 6867.11,1101.28 r180 top value="0.1 u"
C113 "SM-1206, 10%, 10v, X7R" CAPC3216N 6569.85,2152.46 r0 top value=22u
C114 "SM-0402, 10%, 10v" CAPC1005X06A#2 6867.09,2124.9 r180 top value="0.1 u"
C115 "C0402C104K8PACTU" CAPC1005X06A#2 6177.17,-1425.2 r180 top value="0.1 u"
C116 "LMK105BJ105KV-F" CAPC1005X06A#2 6177.17,-1389.76 r180 top value=1u
C117 "C0402C104K8PACTU" CAPC1005X06A#2 5791.34,-1681.1 r90 top value="0.1 u"
C118 "C0402C104K8PACTU" CAPC1005X06A#2 6177.17,-1681.1 r180 top value="0.1 u"
C119 "LMK105BJ105KV-F" CAPC1005X06A#2 6177.17,-1645.67 r180 top value=1u
D1 "POWER" CD1608-0603-PIN1-CATHODE 937.01,2342.52 r180 top
FID1 "FIDUCIAL" FID1MM/2MM-SS 334.65,2881.89 r90 top
FID2 "FIDUCIAL" FID1MM/2MM-SS 8947.7,2804.24 r90 top
FID3 "FIDUCIAL" FID1MM/2MM-SS 9251.97,-2480.31 r90 top
FID4 "FIDUCIAL" FID1MM/2MM-SS 456.69,-2791.34 r90 top
FID5 "FIDUCIAL" FID1MM/2MM-SS 703.7,1417.24 r90 top
FID6 "FIDUCIAL" FID1MM/2MM-SS 5779.53,1566.93 r90 top
FID7 "FIDUCIAL" FID1MM/2MM-SS 5594.49,-1744.09 r90 top
FID8 "FIDUCIAL" FID1MM/2MM-SS 808.7,-1545.76 r90 top
J1 "QSE-020-01-F-D-A" QSE-020-01-X-D-A-L-SYZYGY 1850.44,2755.91 r180 top locked
J2 "QSE-020-01-F-D-A" QSE-020-01-X-D-A-L-SYZYGY 3700.84,2755.91 r180 top locked
J3 "87831-1420" XILINX-JTAG 157.48,-2161.42 r90 top
J4 "QSE-020-01-F-D-A" QSE-020-01-X-D-A-L-SYZYGY 1456.69,-2755.91 r0 top locked
J5 "QSE-020-01-F-D-A" QSE-020-01-X-D-A-L-SYZYGY 3307.09,-2755.91 r0 top locked
J6 "RXP0" SMA 7371.72,-1170.11 r270 top
J7 "TXP0" SMA 7962.27,-1170.11 r270 top
J8 "QSH-020-01-F-D-DP-A" QSH-020-01-X-D-DP-A-L-SYZYGY 7795.43,2756.02 r180 top locked
J9 "RXN0" SMA 7371.72,-1760.66 r270 top
J10 "TXN0" SMA 7962.27,-1760.66 r270 top
J11 "RXP1" SMA 8552.82,-1170.11 r270 top
J12 "TXP1" SMA 9143.37,-1170.11 r270 top
J13 "RXN1" SMA 8552.82,-1760.66 r270 top
J14 "TXN1" SMA 9143.37,-1760.66 r270 top
J15 "RXP0" UFL-R-SMT-1 8925.2,-2279.53 r270 top
J16 "TXP0" UFL-R-SMT-1 8216.54,-2279.53 r270 top
J17 "RXN0" UFL-R-SMT-1 8610.24,-2279.53 r90 top
J18 "TXN0" UFL-R-SMT-1 7901.57,-2279.53 r90 top
J19 "RXP1" UFL-R-SMT-1 8925.2,-2712.6 r270 top
J20 "TXP1" UFL-R-SMT-1 8216.54,-2712.6 r270 top
J21 "RXN1" UFL-R-SMT-1 8610.24,-2712.6 r90 top
J22 "TXN1" UFL-R-SMT-1 7901.57,-2712.6 r90 top
J23 "QSH-020-01-F-D-DP-A" QSH-020-01-X-D-DP-A-L-SYZYGY 5748.19,2756.02 r180 top locked
J24 "0455580003" 0455580003 462.55,2043.31 r90 top
J26 "67800-5005" MOLEX-67800-5005 6673.23,-1200.79 r0 top
J27 "67800-5005" MOLEX-67800-5005 6673.23,-1751.97 r180 top
J28 "PJ-102AH" CUI-PJ102A 566.93,3043.31 r180 top
J30 "FS1-Z38-20Z6-60" QSFP28_RECEPTACLE_SFF-8679 7492.13,161.42 r90 top locked
J31 "FS1-Z38-20Z6-60" QSFP28_RECEPTACLE_SFF-8679 7492.11,1185.04 r90 top locked
J32 "MDT420M01001" M2-CONNECTOR_M-KEYING 6149.61,-437.01 r90 top locked
JSO1 "Jack Screw Standoff" JSO-0515-01 2559.06,1437.01 r0 top locked
JSO2 "Jack Screw Standoff" JSO-0515-01 5472.44,1437.01 r0 top locked
JSO3 "Jack Screw Standoff" JSO-0515-01 2559.06,-1437.01 r0 top locked
JSO4 "Jack Screw Standoff" JSO-0515-01 5472.44,-1437.01 r0 top locked
L1 "XAL6030-222MEB" XAL60XX 1651.47,-2226.66 r0 top value=2.2u
L2 "XAL6030-222MEB" XAL60XX 1651.47,-1911.66 r0 top value=2.2u
L3 "VLS4012CX-2R2M-1" VLS4012CX 799.36,-1925.86 r180 top value=2.2u
L4 "VLS4012CX-2R2M-1" VLS4012CX 799.36,-2240.14 r180 top value=2.2u
L5 "CIGT252010LM1R0MNE" CIGT252010 6670.26,1014.66 r270 top value=1u
L6 "CIGT252010LM1R0MNE" CIGT252010 6809.04,1014.66 r270 top value=1u
L7 "CIGT252010LM1R0MNE" CIGT252010 6525.57,1014.66 r270 top value=1u
L8 "CIGT252010LM1R0MNE" CIGT252010 6670.24,2038.28 r270 top value=1u
L9 "CIGT252010LM1R0MNE" CIGT252010 6809.02,2038.28 r270 top value=1u
L10 "CIGT252010LM1R0MNE" CIGT252010 6525.56,2038.28 r270 top value=1u
MC1 "QTH-090-01-F-D-A" QTH-090-01-X-D 4015.76,1437.02 r0 top locked
MC1A "0877584016" HDR2X20-2MM 4370.08,2125.98 r0 top
MC1B "Header, 20-Pin, Single Row" HDR1X20-2MM 4370.08,2007.87 r0 top
MC2 "QTH-090-01-F-D-A" QTH-090-01-X-D 4015.76,-1436.99 r0 top locked
MC2A "0877584016" HDR2X20-2MM 5098.43,-2720.47 r0 top
MC2B "0877584016" HDR2X20-2MM 6830.71,-2720.47 r0 top
MC2C "Header, 20-Pin, Single Row" HDR1X20-2MM 5098.43,-2838.58 r0 top
MC2D "Header, 20-Pin, Single Row" HDR1X20-2MM 6830.71,-2838.58 r0 top
MC3 "QTH-060-01-L-D-DP-A" QTH-060-01-X-D-DP-A 5472.46,0.02 r270 top locked
MH1 "MTG" MTG-3.2/6.5-PTH 157.48,1515.75 r0 top
MH2 "MTG" MTG-3.2/6.5-PTH 157.48,-1515.75 r0 top
MH5 "MTG" MTG-3.2/6.5-PTH 196.85,2755.91 r0 top locked
MH6 "MTG" MTG-3.2/6.5-PTH 9251.97,2755.91 r0 top locked
MH7 "MTG" MTG-3.2/6.5-PTH 9251.97,-2755.91 r0 top locked
MH8 "MTG" MTG-3.2/6.5-PTH 196.85,-2755.91 r0 top locked
Q1 "2.2A, 30V" SOT23-95P240X110 1187.06,2308.92 r90 top
QSFP1 "Pressfit" QSFP28_SINGLE_CAGE 7492.13,161.42 r90 top locked
QSFP2 "Pressfit" QSFP28_SINGLE_CAGE 7492.11,1185.04 r90 top locked
R1 "CRCW0402210KFKED" RESC1005X06A 2136.22,2521.24 r180 top value="210 k"
R2 "CRCW040284K5FKED" RESC1005X06A 4153.54,2523.62 r180 top value="84.5 k"
R3 "SM-0402, 1%, 1/16W" RESC1005X06A 2240.16,1716.54 r0 top value="10.0 k"
R4 "SM-0402, 1%, 1/16W" RESC1005X06A 2240.16,1794.54 r0 top value="10.0 k"
R5 "SM-0402, 1%, 1/16W" RESC1005X06A 2240.16,1872.54 r0 top value="10.0 k"
R6 "SM-0402, 1%, 1/16W" RESC1005X06A 2240.16,1755.54 r180 top value="10.0 k"
R7 "SM-0402, 1%, 1/16W" RESC1005X06A 2240.16,1833.54 r180 top value="10.0 k"
R8 "SM-0402, 1%, 1/16W" RESC1005X06A 2240.16,1911.54 r180 top value="10.0 k"
R9 "RC0402FR-078K87L" RESC1005X06A 3021.72,-2525.76 r0 top value="8.87 k"
R10 "RC0402FR-076K98L" RESC1005X06A 1171,-2516.76 r0 top value="6.98 k"
R11 "SM-0402, 1%, 1/16W" RESC1005X06A 5791.34,-990.16 r270 top value=100
R12 "CRCW040234K0FKED" RESC1005X06A 8078.5,2525.87 r180 top value="34 k"
R13 "CRCW040249K9FKED" RESC1005X06A 6033.62,2528.87 r180 top value=49.9k
R14 "CRCW040210K0FKED" RESC1005X06A 1085.74,-2349.16 r270 top value="10.0 k"
R15 "CRCW040210K0FKED" RESC1005X06A 1202.1,-1795.16 r90 top value="10.0 k"
R16 "SM-0402, 1%, 1/16W" RESC1005X06A 1355.47,-2276.3 r270 top value="31.6 k"
R17 "SM-0402, 1%, 1/16W" RESC1005X06A 1319.47,-2276.3 r90 top value="10.0 k"
R18 "CRCW040215K0FKED" RESC1005X06A 1275.74,-2290.69 r270 top value="15 k"
R19 "SM-0402, 1%, 1/16W" RESC1005X06A 1424.74,-1863.66 r90 top value="31.6 k"
R20 "SM-0402, 1%, 1/16W" RESC1005X06A 1388.74,-1863.66 r270 top value="10.0 k"
R21 "CRCW040215K0FKED" RESC1005X06A 1341.27,-1871.66 r90 top value="15 k"
R22 "SM-0402, 1%, 1/16W" RESC1005X06A 922.74,-1902.66 r90 top value="31.6 k"
R23 "CRCW040215K0FKED" RESC1005X06A 1034.74,-1902.66 r90 top value="15 k"
R24 "SM-0402, 1%, 1/16W" RESC1005X06A 998.74,-1902.66 r270 top value="10.0 k"
R25 "CRCW040239K2FKED" RESC1005X06A 1123.54,-2349.16 r90 top value="39.2 k"
R26 "SM-0402, 1%, 1/16W" RESC1005X06A 929.74,-2256.38 r270 top value="52.3 k"
R27 "CRCW040215K0FKED" RESC1005X06A 1047.74,-2273.66 r270 top value="15 k"
R28 "CRCW0402374KFKED" RESC1005X06A 1161.47,-2276.58 r90 top value="374 k"
R29 "SM-0402, 1%, 1/16W" RESC1005X06A 1005.74,-2256.66 r90 top value="10.0 k"
R30 "CRCW04022K00FKED" RESC1005X06A 1165.35,2405.51 r0 top value="2.0 k"
R31 "CRCW040210K0FKED" RESC1005X06A 1322.83,-1740.16 r180 top value="10.0 k"
R32 "CRCW04024K75FKED" RESC1005X06A 5787.4,-1232.28 r180 top value="4.75 k"
R33 "CRCW04024K75FKED" RESC1005X06A 5787.4,-1267.72 r180 top value="4.75 k"
R34 "CRCW04024K75FKED" RESC1005X06A 5787.4,-1303.15 r180 top value="4.75 k"
R35 "CRCW04024K75FKED" RESC1005X06A 6165.35,-1232.28 r0 top value="4.75 k"
R36 "CRCW04024K75FKED" RESC1005X06A 6165.35,-1267.72 r0 top value="4.75 k"
R37 "CRCW04024K75FKED" RESC1005X06A 6165.35,-1303.15 r0 top value="4.75 k"
R38 "CRCW04024K75FKED" RESC1005X06A 6177.17,-1460.63 r0 top value="4.75 k"
R39 "CRCW04024K75FKED" RESC1005X06A 6177.17,-1496.06 r0 top value="4.75 k"
R40 "SM-0402, 1%, 1/16W" RESC1005X06A 6047.24,-1010.89 r180 top value=0
R41 "CRCW04024K75FKED" RESC1005X06A 6177.17,-1531.5 r0 top value="4.75 k"
R42 "CRCW04024K75FKED" RESC1005X06A 8978.35,2303.15 r0 top value="4.75 k"
R43 "CRCW04024K75FKED" RESC1005X06A 8346.2,2205.94 r90 top value="4.75 k"
R44 "CRCW04024K75FKED" RESC1005X06A 8807.09,2129.92 r270 top value="4.75 k"
R45 "CRCW04024K75FKED" RESC1005X06A 8858.27,2129.92 r270 top value="4.75 k"
R46 "CRCW04024K75FKED" RESC1005X06A 8858.27,2027.56 r270 top value="4.75 k"
R47 "CRCW04024K75FKED" RESC1005X06A 8807.09,2027.56 r270 top value="4.75 k"
R48 "CRCW04024K75FKED" RESC1005X06A 8438.74,2027.67 r270 top value="4.75 k"
R49 "CRCW04024K75FKED" RESC1005X06A 8391.5,2027.67 r270 top value="4.75 k"
R50 "CRCW04024K75FKED" RESC1005X06A 8438.74,2130.03 r270 top value="4.75 k"
R51 "CRCW04024K75FKED" RESC1005X06A 8391.5,2130.03 r270 top value="4.75 k"
R52 "CRCW04024K75FKED" RESC1005X06A 8978.35,2066.93 r0 top value="4.75 k"
R53 "CRCW04024K75FKED" RESC1005X06A 7948.56,2205.94 r90 top value="4.75 k"
R54 "CRCW04024K75FKED" RESC1005X06A 6177.17,-1566.93 r0 top value="4.75 k"
R55 "CRCW04024K75FKED" RESC1005X06A 6177.17,-1716.54 r0 top value="4.75 k"
R56 "CRCW04024K75FKED" RESC1005X06A 6177.17,-1751.97 r0 top value="4.75 k"
R57 "CRCW04024K75FKED" RESC1005X06A 6177.17,-1787.4 r0 top value="4.75 k"
R58 "CRCW040210K0FKED" RESC1005X06A 7590.55,2196.85 r90 top value="10.0 k"
R59 "SM-0402, 1%, 1/16W" RESC1005X06A 6100.24,-991.73 r270 top value=49.9
R60 "SM-0402, 1%, 1/16W" RESC1005X06A 6100.24,-1065.88 r90 top value=49.9
R61 "SM-0402, 1%, 1/16W" RESC1005X06A 6047.24,-1048.17 r180 top value=0
R62 "SM-0402, 1%, 1/16W" RESC1005X06A 7590.55,2110.24 r90 top value=0
R63 "CRCW040210K0FKED" RESC1005X06A 7590.55,2027.56 r90 top value="10.0 k"
R64 "CRCW040210K0FKED" RESC1005X06A 6267.72,-929.13 r0 top value="10.0 k"
R65 "SM-0402, 1%, 1/16W" RESC1005X06A 6267.72,-976.38 r0 top value=0
R66 "CRCW040210K0FKED" RESC1005X06A 6267.72,-1023.62 r0 top value="10.0 k"
SO1 "Standoff" 9774025151R-NO-PASTE 7261.81,-437.01 r90 top
SO2 "Standoff" 9774025151R-NO-PASTE 7734.25,-437.01 r90 top
SO3 "Standoff" 9774025151R-NO-PASTE 8442.91,-437.01 r90 top
SO4 "Standoff" 9774025151R 9230.31,-437.01 r0 top
TP1 "VIO1" TP-PTH-65/100#1 4787.4,2346.46 r0 top
TP2 "+VDCIN" TP-PTH-65/100#1 196.85,2440.94 r0 top
TP3 "VIO2" TP-PTH-65/100#2 2755.78,-2087.1 r0 top
TP4 "+3.3VDD" TP-PTH-65/100#1 1417.32,2283.46 r0 top
TP6 "VREF1" TP-PTH-65/100#1 1417.32,1811.02 r0 top
TP7 "+1.8VDD" TP-PTH-65/100#1 1417.32,2047.24 r0 top
TP9 "VREF2" TP-PTH-65/100#1 2440.94,-2086.61 r90 top
TP10 "DGND" TP-PTH-65/100#1 9251.97,-2322.83 r90 top
TP12 "VCCBATT" TP-PTH-65/100#1 3070.74,-2086.61 r90 top
TP13 "DGND" TP-PTH-65/100#3 9252.41,2245.07 r90 top
TP15 "DGND" TP-PTH-65/100#1 3385.7,-2086.61 r90 top
TP17 "+3.3V_QSFP" TP-SMD40 1963.1,-2292.99 r270 top
TP18 "+3.3V_M.2" TP-SMD40 1963.1,-1851.87 r90 top
TP19 "+3.3V_SZG" TP-SMD40 524.14,-1821.04 r180 top
TP20 "+5V_SZG" TP-SMD40 566.93,-2417.32 r90 top
TP21 "TESTPOINT-SMD40" TP-SMD40 1161.42,-2421.26 r90 top
U1 "24FC256-I/SN" SO-G8 1968.06,1859.26 r90 top
U2 "DSC557-053344KL1T" DSC557-05 5921.26,-1029.53 r90 top
U3 "TPS65400RGZT" PVQFN-48 1212.74,-2082.66 r180 top
U4 "MAX3378EEUD+" MAX3378EEUD+ 5976.38,-1279.53 r270 top
U5 "MAX3378EEUD+" MAX3378EEUD+ 5976.38,-1511.81 r270 top
U7 "SN74AXC1T45DCK" DCK-R-PDSO-G6 8978.35,2397.64 r180 top
U8 "MAX3378EEUD+" MAX3378EEUD+ 8172.24,2084.65 r270 top
U9 "MAX3378EEUD+" MAX3378EEUD+ 8623.03,2084.65 r270 top
U10 "SN74AXC1T45DCK" DCK-R-PDSO-G6 8978.35,2165.35 r180 top
U11 "MAX3378EEUD+" MAX3378EEUD+ 7774.61,2084.65 r270 top
U12 "MAX3378EEUD+" MAX3378EEUD+ 5976.38,-1744.09 r270 top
